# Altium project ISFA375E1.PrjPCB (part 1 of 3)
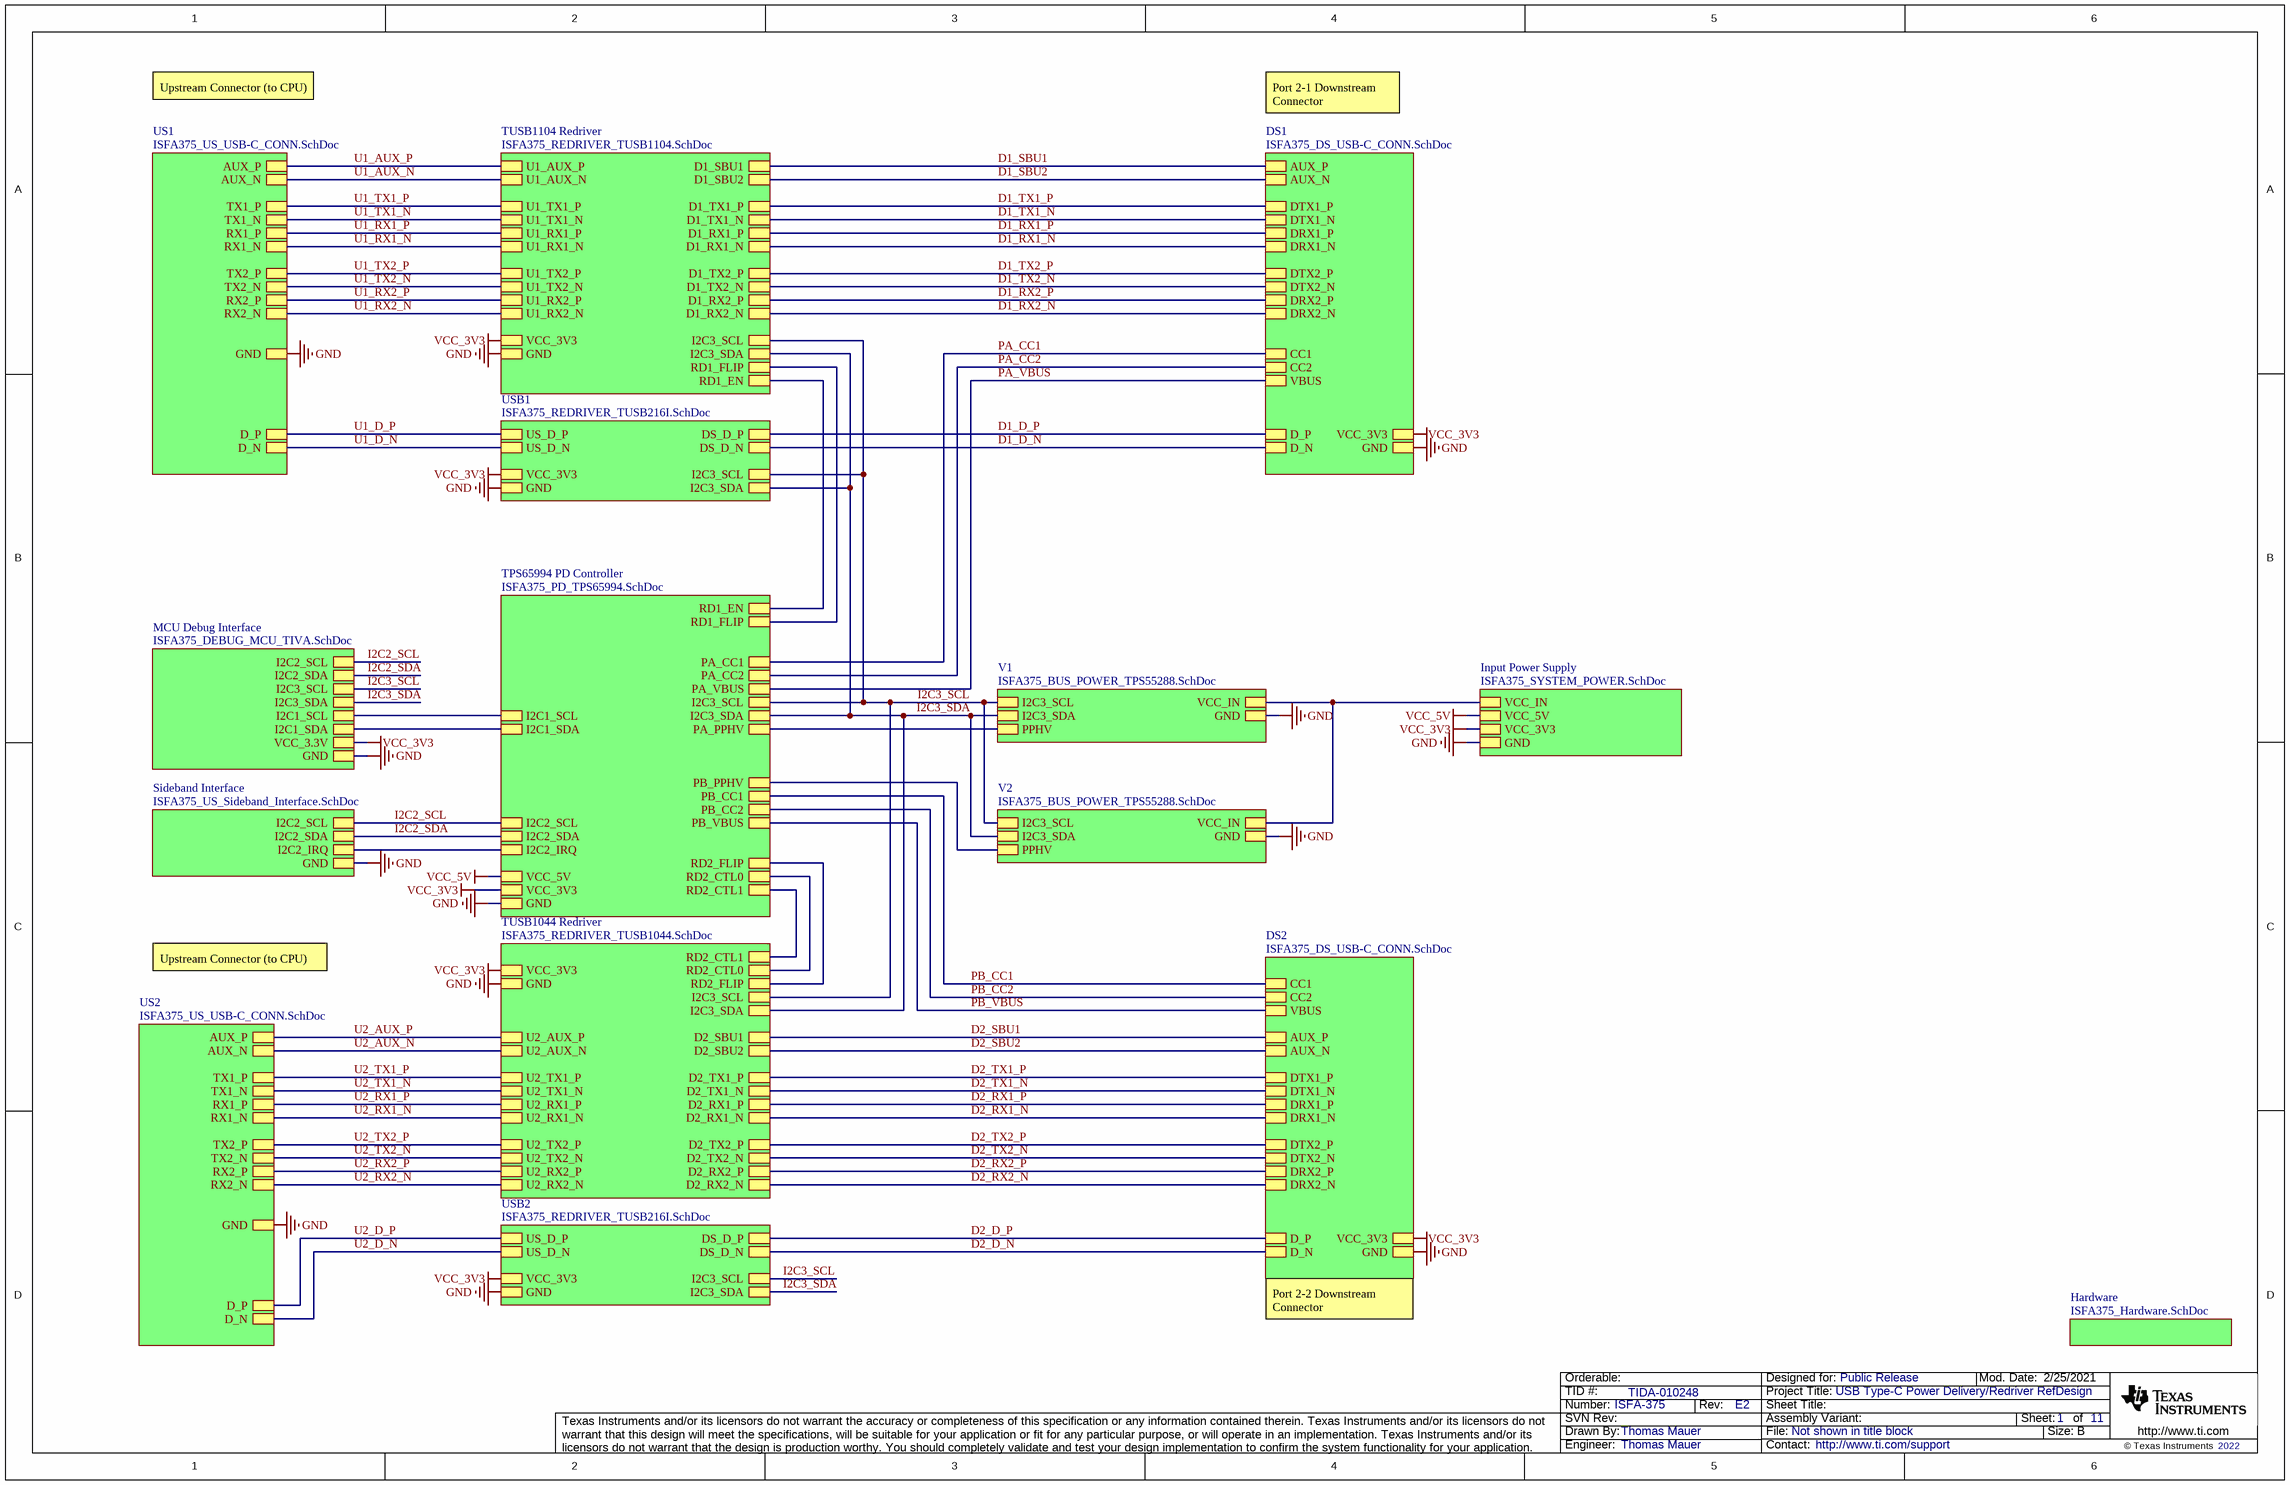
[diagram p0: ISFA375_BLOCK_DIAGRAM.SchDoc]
CopyrightYear: 2022; PCB_Layout: Preeti Udapudi; PCB_Rev: E2; PRJ_Customer: Public Release; PRJ_Engineer: Thomas Mauer; PRJ_Number: ISFA-375; PRJ_Title: USB Type-C Power Delivery/Redriver RefDesign; SCH_Rev: E2; TechSupport: http://www.ti.com/support; TID: TIDA-010248
12 sheets, 488 parts. Net scope: hierarchical (ports join the sheet entries above them; power ports are global).
Board file: ISFA375.PcbDoc
Sheets:
  ISFA375_BLOCK_DIAGRAM.SchDoc
    US1 = ISFA375_US_USB-C_CONN.SchDoc
    TPS65994 PD Controller = ISFA375_PD_TPS65994.SchDoc
    MCU Debug Interface = ISFA375_DEBUG_MCU_TIVA.SchDoc
    DS1 = ISFA375_DS_USB-C_CONN.SchDoc
    Input Power Supply = ISFA375_SYSTEM_POWER.SchDoc
    V1 = ISFA375_BUS_POWER_TPS55288.SchDoc
    V2 = ISFA375_BUS_POWER_TPS55288.SchDoc
    TUSB1104 Redriver = ISFA375_REDRIVER_TUSB1104.SchDoc
    TUSB1044 Redriver = ISFA375_REDRIVER_TUSB1044.SchDoc
    Hardware = ISFA375_Hardware.SchDoc
    Sideband Interface = ISFA375_US_Sideband_Interface.SchDoc
    USB1 = ISFA375_REDRIVER_TUSB216I.SchDoc
    USB2 = ISFA375_REDRIVER_TUSB216I.SchDoc
    US2 = ISFA375_US_USB-C_CONN.SchDoc
    DS2 = ISFA375_DS_USB-C_CONN.SchDoc

## Sheet ISFA375_BLOCK_DIAGRAM.SchDoc
size 431 x 279 mm; Date: Not shown in title block; ApprovedBy: Not shown in title block; CheckedBy: Not shown in title block; Author: Not shown in title block; CompanyName: Not shown in title block; DrawnBy: Thomas Mauer; Engineer: Not shown in title block; Organization: Not shown in title block; Address1: Not shown in title block; Address2: Not shown in title block; Address3: Not shown in title block; Address4: Not shown in title block; DocumentNumber: 1; Revision: Use project parameter SCH_Rev; SheetNumber: 1; SheetTotal: 11; PageSetup: Record=PageOptions¦CenterHorizontal=True¦CenterVertical=True¦PrintScale=1.00¦XCorrection=1.00¦YCorrection=1.00¦PrintKind=0¦BorderSize=5000000¦LeftOffset=0¦BottomOffset=0¦Orientation=2¦PaperLength=1000¦PaperWidth=1000¦Scale=100¦PaperSource=15¦PrintQuality=600¦MediaType=1¦DitherType=10¦PaperKind=Letter¦PrintScaleMode=1

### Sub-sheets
DS1 = ISFA375_DS_USB-C_CONN.SchDoc: VBUS, AUX_P, AUX_N, DTX1_P, DTX1_N, DRX1_P, DRX1_N, DTX2_P, DTX2_N, DRX2_P, DRX2_N, CC1, CC2, D_P, D_N, GND, VCC_3V3
DS2 = ISFA375_DS_USB-C_CONN.SchDoc: VBUS, AUX_P, AUX_N, DTX1_P, DTX1_N, DRX1_P, DRX1_N, DTX2_P, DTX2_N, DRX2_P, DRX2_N, CC1, CC2, D_P, D_N, GND, VCC_3V3
Hardware = ISFA375_Hardware.SchDoc: no entries
Input Power Supply = ISFA375_SYSTEM_POWER.SchDoc: VCC_IN, VCC_5V, VCC_3V3, GND
MCU Debug Interface = ISFA375_DEBUG_MCU_TIVA.SchDoc: GND, VCC_3.3V, I2C1_SCL, I2C1_SDA, I2C3_SCL, I2C3_SDA, I2C2_SCL, I2C2_SDA
Sideband Interface = ISFA375_US_Sideband_Interface.SchDoc: GND, I2C2_IRQ, I2C2_SCL, I2C2_SDA
TPS65994 PD Controller = ISFA375_PD_TPS65994.SchDoc: PA_VBUS, PB_VBUS, I2C3_SCL, I2C3_SDA, I2C1_SCL, I2C1_SDA, PA_CC1, PA_CC2, PB_PPHV, I2C2_SCL, I2C2_SDA, I2C2_IRQ, PB_CC1, PB_CC2, PA_PPHV, GND, VCC_5V, VCC_3V3, RD1_EN, RD2_CTL0, RD2_CTL1, RD2_FLIP, RD1_FLIP
TUSB1044 Redriver = ISFA375_REDRIVER_TUSB1044.SchDoc: U2_TX1_P, U2_TX1_N, U2_RX1_P, U2_RX1_N, U2_TX2_P, U2_TX2_N, U2_RX2_P, U2_RX2_N, U2_AUX_P, U2_AUX_N, D2_TX1_P, D2_TX1_N, D2_RX1_P, D2_RX1_N, D2_TX2_P, D2_TX2_N, D2_RX2_P, D2_RX2_N, D2_SBU1, D2_SBU2, I2C3_SCL, I2C3_SDA, GND, VCC_3V3, RD2_FLIP, RD2_CTL0, RD2_CTL1
TUSB1104 Redriver = ISFA375_REDRIVER_TUSB1104.SchDoc: U1_TX1_P, U1_TX1_N, U1_RX1_P, U1_RX1_N, U1_TX2_P, U1_TX2_N, U1_RX2_P, U1_RX2_N, U1_AUX_P, U1_AUX_N, D1_TX1_P, D1_TX1_N, D1_RX1_P, D1_RX1_N, D1_TX2_P, D1_TX2_N, D1_RX2_P, D1_RX2_N, D1_SBU1, D1_SBU2, I2C3_SCL, I2C3_SDA, GND, VCC_3V3, RD1_EN, RD1_FLIP
US1 = ISFA375_US_USB-C_CONN.SchDoc: AUX_P, AUX_N, TX1_P, TX1_N, RX1_P, RX1_N, TX2_P, TX2_N, RX2_P, RX2_N, D_P, D_N, GND
US2 = ISFA375_US_USB-C_CONN.SchDoc: AUX_P, AUX_N, TX1_P, TX1_N, RX1_P, RX1_N, TX2_P, TX2_N, RX2_P, RX2_N, D_P, D_N, GND
USB1 = ISFA375_REDRIVER_TUSB216I.SchDoc: US_D_N, US_D_P, DS_D_P, DS_D_N, I2C3_SCL, I2C3_SDA, GND, VCC_3V3
USB2 = ISFA375_REDRIVER_TUSB216I.SchDoc: US_D_N, US_D_P, DS_D_P, DS_D_N, I2C3_SCL, I2C3_SDA, GND, VCC_3V3
V1 = ISFA375_BUS_POWER_TPS55288.SchDoc: I2C3_SCL, I2C3_SDA, VCC_IN, GND, PPHV
V2 = ISFA375_BUS_POWER_TPS55288.SchDoc: PPHV, I2C3_SCL, I2C3_SDA, VCC_IN, GND

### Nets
GND: sheet US1/GND, sheet TPS65994 PD Controller/GND, sheet MCU Debug Interface/GND, sheet DS1/GND, sheet Input Power Supply/GND, sheet V1/GND, sheet V2/GND, sheet TUSB1104 Redriver/GND, sheet TUSB1044 Redriver/GND, sheet Sideband Interface/GND, sheet USB1/GND, sheet USB2/GND, sheet US2/GND, sheet DS2/GND
VCC_3V3: sheet TPS65994 PD Controller/VCC_3V3, sheet MCU Debug Interface/VCC_3.3V, sheet DS1/VCC_3V3, sheet Input Power Supply/VCC_3V3, sheet TUSB1104 Redriver/VCC_3V3, sheet TUSB1044 Redriver/VCC_3V3, sheet USB1/VCC_3V3, sheet USB2/VCC_3V3, sheet DS2/VCC_3V3  [project net VCC_3.3V]
VCC_5V: sheet TPS65994 PD Controller/VCC_5V, sheet Input Power Supply/VCC_5V
VCC_IN: sheet Input Power Supply/VCC_IN, sheet V1/VCC_IN, sheet V2/VCC_IN
D1_D_N: sheet DS1/D_N, sheet USB1/DS_D_N
D1_D_P: sheet DS1/D_P, sheet USB1/DS_D_P
D1_RX1_N: sheet DS1/DRX1_N, sheet TUSB1104 Redriver/D1_RX1_N
D1_RX1_P: sheet DS1/DRX1_P, sheet TUSB1104 Redriver/D1_RX1_P
D1_RX2_N: sheet DS1/DRX2_N, sheet TUSB1104 Redriver/D1_RX2_N
D1_RX2_P: sheet DS1/DRX2_P, sheet TUSB1104 Redriver/D1_RX2_P
D1_SBU1: sheet DS1/AUX_P, sheet TUSB1104 Redriver/D1_SBU1  [project net AUX_P]
D1_SBU2: sheet DS1/AUX_N, sheet TUSB1104 Redriver/D1_SBU2  [project net AUX_N]
D1_TX1_N: sheet DS1/DTX1_N, sheet TUSB1104 Redriver/D1_TX1_N
D1_TX1_P: sheet DS1/DTX1_P, sheet TUSB1104 Redriver/D1_TX1_P
D1_TX2_N: sheet DS1/DTX2_N, sheet TUSB1104 Redriver/D1_TX2_N
D1_TX2_P: sheet DS1/DTX2_P, sheet TUSB1104 Redriver/D1_TX2_P
D2_D_N: sheet USB2/DS_D_N, sheet DS2/D_N  [project net D1_D_N]
D2_D_P: sheet USB2/DS_D_P, sheet DS2/D_P  [project net D1_D_P]
D2_RX1_N: sheet TUSB1044 Redriver/D2_RX1_N, sheet DS2/DRX1_N
D2_RX1_P: sheet TUSB1044 Redriver/D2_RX1_P, sheet DS2/DRX1_P
D2_RX2_N: sheet TUSB1044 Redriver/D2_RX2_N, sheet DS2/DRX2_N
D2_RX2_P: sheet TUSB1044 Redriver/D2_RX2_P, sheet DS2/DRX2_P
D2_SBU1: sheet TUSB1044 Redriver/D2_SBU1, sheet DS2/AUX_P  [project net AUX_P]
D2_SBU2: sheet TUSB1044 Redriver/D2_SBU2, sheet DS2/AUX_N  [project net AUX_N]
D2_TX1_N: sheet TUSB1044 Redriver/D2_TX1_N, sheet DS2/DTX1_N
D2_TX1_P: sheet TUSB1044 Redriver/D2_TX1_P, sheet DS2/DTX1_P
D2_TX2_N: sheet TUSB1044 Redriver/D2_TX2_N, sheet DS2/DTX2_N
D2_TX2_P: sheet TUSB1044 Redriver/D2_TX2_P, sheet DS2/DTX2_P
I2C1_SCL: sheet TPS65994 PD Controller/I2C1_SCL, sheet MCU Debug Interface/I2C1_SCL
I2C1_SDA: sheet TPS65994 PD Controller/I2C1_SDA, sheet MCU Debug Interface/I2C1_SDA
I2C2_IRQ: sheet TPS65994 PD Controller/I2C2_IRQ, sheet Sideband Interface/I2C2_IRQ
I2C2_SCL: sheet TPS65994 PD Controller/I2C2_SCL, sheet MCU Debug Interface/I2C2_SCL, sheet Sideband Interface/I2C2_SCL
I2C2_SDA: sheet TPS65994 PD Controller/I2C2_SDA, sheet MCU Debug Interface/I2C2_SDA, sheet Sideband Interface/I2C2_SDA
I2C3_SCL: sheet TPS65994 PD Controller/I2C3_SCL, sheet MCU Debug Interface/I2C3_SCL, sheet V1/I2C3_SCL, sheet V2/I2C3_SCL, sheet TUSB1104 Redriver/I2C3_SCL, sheet TUSB1044 Redriver/I2C3_SCL, sheet USB1/I2C3_SCL, sheet USB2/I2C3_SCL
I2C3_SDA: sheet TPS65994 PD Controller/I2C3_SDA, sheet MCU Debug Interface/I2C3_SDA, sheet V1/I2C3_SDA, sheet V2/I2C3_SDA, sheet TUSB1104 Redriver/I2C3_SDA, sheet TUSB1044 Redriver/I2C3_SDA, sheet USB1/I2C3_SDA, sheet USB2/I2C3_SDA
PA_CC1: sheet TPS65994 PD Controller/PA_CC1, sheet DS1/CC1
PA_CC2: sheet TPS65994 PD Controller/PA_CC2, sheet DS1/CC2
PA_PPHV: sheet TPS65994 PD Controller/PA_PPHV, sheet V1/PPHV
PA_VBUS: sheet TPS65994 PD Controller/PA_VBUS, sheet DS1/VBUS
PB_CC1: sheet TPS65994 PD Controller/PB_CC1, sheet DS2/CC1
PB_CC2: sheet TPS65994 PD Controller/PB_CC2, sheet DS2/CC2
PB_PPHV: sheet TPS65994 PD Controller/PB_PPHV, sheet V2/PPHV
PB_VBUS: sheet TPS65994 PD Controller/PB_VBUS, sheet DS2/VBUS
RD1_EN: sheet TPS65994 PD Controller/RD1_EN, sheet TUSB1104 Redriver/RD1_EN
RD1_FLIP: sheet TPS65994 PD Controller/RD1_FLIP, sheet TUSB1104 Redriver/RD1_FLIP
RD2_CTL0: sheet TPS65994 PD Controller/RD2_CTL0, sheet TUSB1044 Redriver/RD2_CTL0
RD2_CTL1: sheet TPS65994 PD Controller/RD2_CTL1, sheet TUSB1044 Redriver/RD2_CTL1
RD2_FLIP: sheet TPS65994 PD Controller/RD2_FLIP, sheet TUSB1044 Redriver/RD2_FLIP
U1_AUX_N: sheet US1/AUX_N, sheet TUSB1104 Redriver/U1_AUX_N  [project net AUX_N]
U1_AUX_P: sheet US1/AUX_P, sheet TUSB1104 Redriver/U1_AUX_P  [project net AUX_P]
U1_D_N: sheet US1/D_N, sheet USB1/US_D_N  [project net D_N]
U1_D_P: sheet US1/D_P, sheet USB1/US_D_P  [project net D_P]
U1_RX1_N: sheet US1/RX1_N, sheet TUSB1104 Redriver/U1_RX1_N  [project net RX1_N]
U1_RX1_P: sheet US1/RX1_P, sheet TUSB1104 Redriver/U1_RX1_P  [project net RX1_P]
U1_RX2_N: sheet US1/RX2_N, sheet TUSB1104 Redriver/U1_RX2_N  [project net RX2_N]
U1_RX2_P: sheet US1/RX2_P, sheet TUSB1104 Redriver/U1_RX2_P  [project net RX2_P]
U1_TX1_N: sheet US1/TX1_N, sheet TUSB1104 Redriver/U1_TX1_N  [project net TX1_N]
U1_TX1_P: sheet US1/TX1_P, sheet TUSB1104 Redriver/U1_TX1_P  [project net TX1_P]
U1_TX2_N: sheet US1/TX2_N, sheet TUSB1104 Redriver/U1_TX2_N  [project net TX2_N]
U1_TX2_P: sheet US1/TX2_P, sheet TUSB1104 Redriver/U1_TX2_P  [project net TX2_P]
U2_AUX_N: sheet TUSB1044 Redriver/U2_AUX_N, sheet US2/AUX_N  [project net AUX_N]
U2_AUX_P: sheet TUSB1044 Redriver/U2_AUX_P, sheet US2/AUX_P  [project net AUX_P]
U2_D_N: sheet USB2/US_D_N, sheet US2/D_N  [project net D_N]
U2_D_P: sheet USB2/US_D_P, sheet US2/D_P  [project net D_P]
U2_RX1_N: sheet TUSB1044 Redriver/U2_RX1_N, sheet US2/RX1_N  [project net RX1_N]
U2_RX1_P: sheet TUSB1044 Redriver/U2_RX1_P, sheet US2/RX1_P  [project net RX1_P]
U2_RX2_N: sheet TUSB1044 Redriver/U2_RX2_N, sheet US2/RX2_N  [project net RX2_N]
U2_RX2_P: sheet TUSB1044 Redriver/U2_RX2_P, sheet US2/RX2_P  [project net RX2_P]
U2_TX1_N: sheet TUSB1044 Redriver/U2_TX1_N, sheet US2/TX1_N  [project net TX1_N]
U2_TX1_P: sheet TUSB1044 Redriver/U2_TX1_P, sheet US2/TX1_P  [project net TX1_P]
U2_TX2_N: sheet TUSB1044 Redriver/U2_TX2_N, sheet US2/TX2_N  [project net TX2_N]
U2_TX2_P: sheet TUSB1044 Redriver/U2_TX2_P, sheet US2/TX2_P  [project net TX2_P]

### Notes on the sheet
- Upstream Connector (to CPU)
- Port 2-1 Downstream Connector
- Port 2-2 Downstream Connector

## Sheet ISFA375_US_USB-C_CONN.SchDoc
size 431 x 279 mm; Date: Not shown in title block; ApprovedBy: Not shown in title block; CheckedBy: Not shown in title block; Author: Not shown in title block; CompanyName: Not shown in title block; DrawnBy: Thomas Mauer; Engineer: Not shown in title block; Organization: Not shown in title block; Address1: Not shown in title block; Address2: Not shown in title block; Address3: Not shown in title block; Address4: Not shown in title block; DocumentNumber: 2; Revision: Use project parameter SCH_Rev; SheetNumber: 2; SheetTotal: 11; PageSetup: Record=PageOptions¦CenterHorizontal=True¦CenterVertical=True¦PrintScale=1.00¦XCorrection=1.00¦YCorrection=1.00¦PrintKind=0¦BorderSize=5000000¦LeftOffset=0¦BottomOffset=0¦Orientation=2¦PaperLength=1000¦PaperWidth=1000¦Scale=100¦PaperSource=15¦PrintQuality=600¦MediaType=1¦DitherType=10¦PaperKind=Letter¦PrintScaleMode=1
Used 2 times, as channels US1, US2. Parts and nets are listed once, with the designators drawn on the sheet.
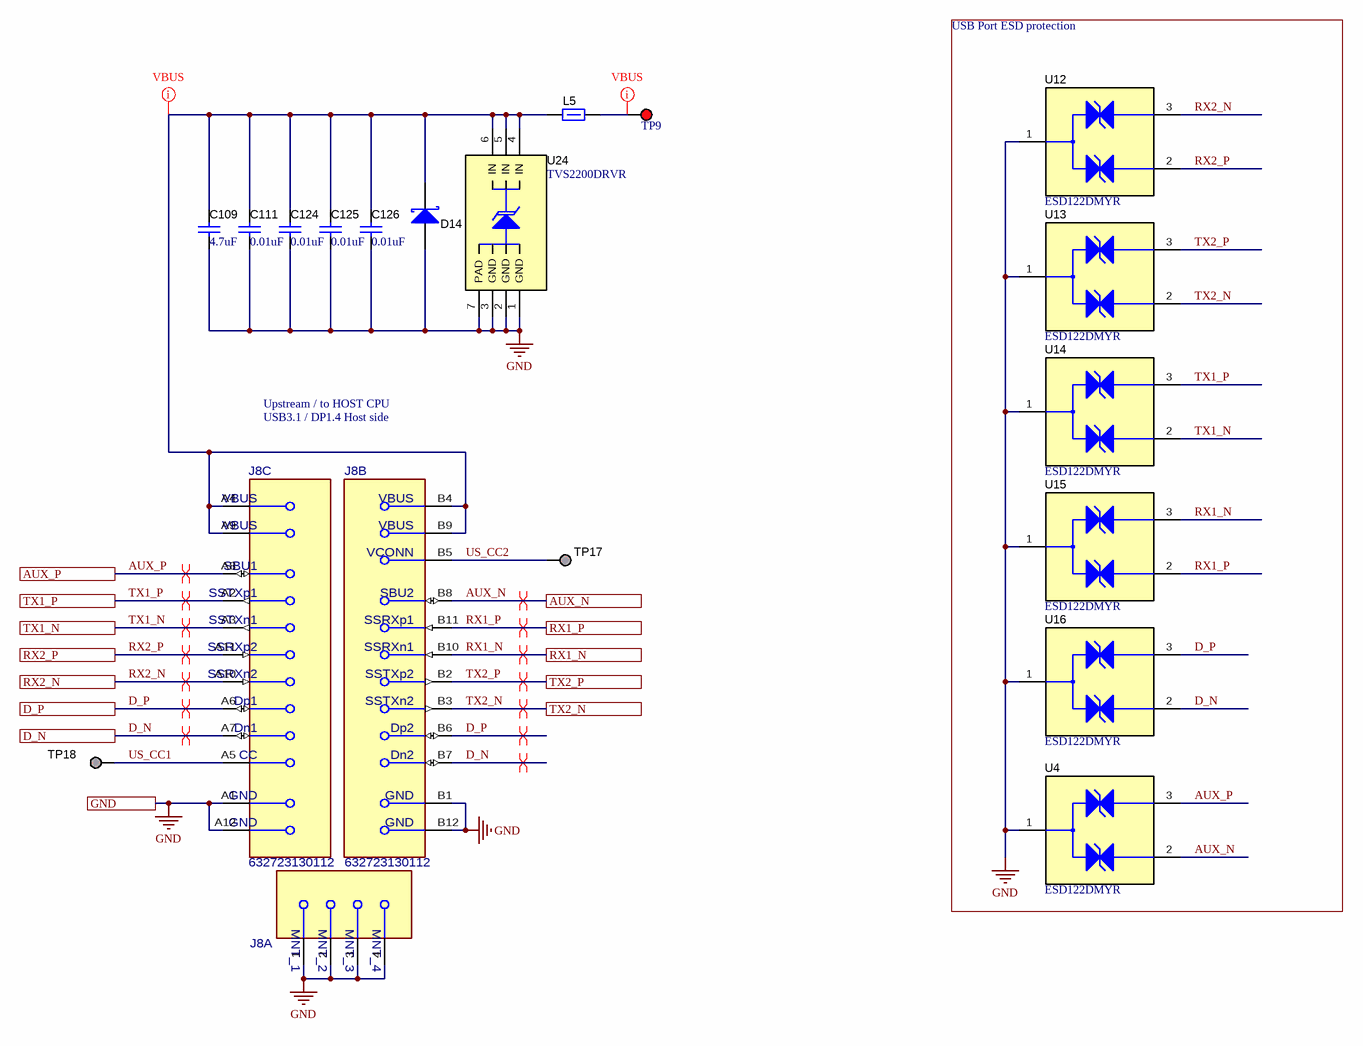
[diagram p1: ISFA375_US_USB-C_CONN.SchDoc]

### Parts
C109  ValueDisplayed: 4.7uF  [0603L]  (hidden comment: GRM188R6YA475KE15D)
C111  ValueDisplayed: 0.01uF  [0402L]  (hidden comment: C0402C103J5RACTU)
C124  ValueDisplayed: 0.01uF  [0402L]  (hidden comment: C0402C103J5RACTU)
C125  ValueDisplayed: 0.01uF  [0402L]  (hidden comment: C0402C103J5RACTU)
C126  ValueDisplayed: 0.01uF  [0402L]  (hidden comment: C0402C103J5RACTU)
D14  NSR20F30NXT5G  [DSN2_0603]  (value not drawn)
J8  632723130112  [FP-632723130112_CONN_USB_9MM65_10MM0-MFG]  (value not drawn)  (parts A,B,C of 3)
L5  742792021  [0805L]  (value not drawn)
TP9  5005  [Keystone5005]  (value not drawn)
TP17  TESTPOINT  [TP_25MIL-SMT]  (value not drawn)  (no BOM)
TP18  TESTPOINT  [TP_25MIL-SMT]  (value not drawn)  (no BOM)
U4  ESD122DMYR  [DMY0003A]
U12  ESD122DMYR  [DMY0003A]
U13  ESD122DMYR  [DMY0003A]
U14  ESD122DMYR  [DMY0003A]
U15  ESD122DMYR  [DMY0003A]
U16  ESD122DMYR  [DMY0003A]
U24  TVS2200DRVR  [DRV0006A]

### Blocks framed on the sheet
USB Port ESD protection: U4 U12-U16

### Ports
AUX_N, AUX_P, D_N, D_P, GND, RX1_N, RX1_P, RX2_N, RX2_P, TX1_N, TX1_P, TX2_N, TX2_P

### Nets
GND: C109.2 C111.2 C124.2 C125.2 C126.2 D14.2(A) J8.1(MNT_1) J8.2(MNT_2) J8.3(MNT_3) J8.4(MNT_4) J8.A1(GND) J8.A12(GND) J8.B1(GND) J8.B12(GND) U4.1(GND) U12.1(GND) U13.1(GND) U14.1(GND) U15.1(GND) U16.1(GND) U24.1(GND) U24.2(GND) U24.3(GND) U24.7(PAD) ; port GND
AUX_N: J8.B8(SBU2) U4.2(IO2) ; port AUX_N
AUX_P: J8.A8(SBU1) U4.3(IO1) ; port AUX_P
D_N: J8.A7(Dn1) J8.B7(Dn2) U16.2(IO2) ; port D_N
D_P: J8.A6(Dp1) J8.B6(Dp2) U16.3(IO1) ; port D_P
RX1_N: J8.B10(SSRXn1) U15.3(IO1) ; port RX1_N
RX1_P: J8.B11(SSRXp1) U15.2(IO2) ; port RX1_P
RX2_N: J8.A10(SSRXn2) U12.3(IO1) ; port RX2_N
RX2_P: J8.A11(SSRXp2) U12.2(IO2) ; port RX2_P
TX1_N: J8.A3(SSTXn1) U14.2(IO2) ; port TX1_N
TX1_P: J8.A2(SSTXp1) U14.3(IO1) ; port TX1_P
TX2_N: J8.B3(SSTXn2) U13.2(IO2) ; port TX2_N
TX2_P: J8.B2(SSTXp2) U13.3(IO1) ; port TX2_P
US_CC1: J8.A5(CC) TP18.1
US_CC2: J8.B5(VCONN) TP17.1
NetC109_1: C109.1 C111.1 C124.1 C125.1 C126.1 D14.1(K) J8.A4(VBUS) J8.A9(VBUS) J8.B4(VBUS) J8.B9(VBUS) L5.1 U24.4(IN) U24.5(IN) U24.6(IN)
NetL5_2: L5.2 TP9.1

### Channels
US1: designators end in _US1; ports AUX_N=AUX_N AUX_P=AUX_P D_N=D_N D_P=D_P GND=GND RX1_N=RX1_N RX1_P=RX1_P RX2_N=RX2_N RX2_P=RX2_P TX1_N=TX1_N TX1_P=TX1_P TX2_N=TX2_N TX2_P=TX2_P
US2: designators end in _US2; ports AUX_N=AUX_N AUX_P=AUX_P D_N=D_N D_P=D_P GND=GND RX1_N=RX1_N RX1_P=RX1_P RX2_N=RX2_N RX2_P=RX2_P TX1_N=TX1_N TX1_P=TX1_P TX2_N=TX2_N TX2_P=TX2_P

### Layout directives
differential pair; net class Diff_pairs: AUX_N, AUX_P, D_N, D_P, RX1_N, RX1_P, RX2_N, RX2_P, TX1_N, TX1_P, TX2_N, TX2_P
net class vbus: NetC109_US1_1, NetL5_US1_2

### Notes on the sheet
- USB3.1 / DP1.4 Host side
- Upstream / to HOST CPU

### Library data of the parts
C109 = CMP-0007357-5: CAP, CERM, 4.7 uF, 35 V, +/- 10%, X5R, 0603; Manufacturer: MuRata; TaMin_C: -55°C; Polarized: N; SizeAreaWB_mm2: 4.68; Value1: Unknown; U/M: EA; Value: 4.7uF; TaMax_C: 85°C; SizeZ_mm: 1; SizeX_mm: 1.6; SizeY_mm: 0.8; Cap_Case: 0603; Value2: 35V; SizeArea_mm2: 1.28; Cap_F: 4.7µF; AEC Category: Q200
C111 C124-C126 = CMP-0006236-2: CAP, CERM, 0.01 uF, 50 V, +/- 5%, X7R, 0402; Manufacturer: Kemet; TaMin_C: -55°C; Polarized: N; SizeAreaWB_mm2: 3; Value1: Unknown; U/M: EA; Value: 0.01uF; TaMax_C: 125°C; SizeZ_mm: 0.6; SizeX_mm: 1; SizeY_mm: 0.5; Cap_Case: 0402; Value2: 50V; Cap_F: 10nF; AEC Category: Q200
D14 = CMP-0028829-2: Diode, Schottky, 30 V, 2 A, 2-XFDFN; Manufacturer: ON Semiconductor; Value2: 0.48V; SizeY_mm: 0.8; Value: 30V; TJmax_C: 150°C; Green_Lifecycle: Not Set; SizeAreaWB_mm2: 4.68; Value1: 2A; SizeArea_mm2: 1.28; Green_REACh: Incomplete; AEC Category: Q101; SizeZ_mm: 0.31; Vf_V: 480mV; AEC Qualified: N; SizeX_mm: 1.6
J8 = CMP-0093331-1: USB-C (USB TYPE-C) USB 3.2 Gen 2 (USB 3.1 Gen 2, Superspeed + (USB 3.1)) Receptacle Connector 24 Position Board Edge, Cutout; Surface Mount; Through Hole, Right Angle; Manufacturer: Wurth Electronics; SizeZ_mm: 3.52mm; AEC Qualified: No; Is Female: yes; Usb Standard: USB 3.1; Voltage_V: 20V; Shrouded: true; ContactFinish: Gold,Nickel; Current_A: 5A; Conn Orientation: Horizontal
L5 = CMP-0003072-1: Ferrite Bead, 22 ohm @ 100 MHz, 6 A, 0805; Manufacturer: Wurth Elektronik; Ztyp@1GHz_Ohm: 40.219; ZTyp@100MHz_Ohm: 22; SizeAreaWB_mm2: 6.75; DCR_ohm: 8m; Value1: 0.008 ohm; Value: 22 ohm; Imax_A: 6A; SizeZ_mm: 1.45; SizeX_mm: 2; SizeY_mm: 1.25; SizeArea_mm2: 2.5
TP9 = CMP-0055142-1: Test Point, Compact, Red, TH; Manufacturer: Keystone; CNHeader: FALSE; Green_Lifecycle: Active; Green_REACh: Passed; ContactFinish: Silver; CT: TRUE
TP17 TP18 = CMP-0078143-3: TEST POINT.  No entry in BOM.
U4 U12-U16 = CMP-0013358-2: 2-Channel ESD Protection Diode for USB Type-C and HDMI 2.0, DMY0003A (X1SON-3); Manufacturer: Texas Instruments; SizeX_mm: 0.6; SizeY_mm: 1.3; CompType: IC; SizeZ_mm: 0.4; SizeArea_mm2: 0.78; SizeAreaWB_mm2: 3.68; U/M: EA
U24 = CMP-0077834-1: 22-V Precision Surge Protection Clamp, DRV0006A (WSON-6); Alternate Manufacturer: Texas Instruments; SizeAreaWB_mm2: 9.0; SizeZ_mm: 0.8; SizeX_mm: 2.0; SizeArea_mm2: 4.0; CompType: IC; AEC Qualified: N; AEC Category: Q200

## Sheet ISFA375_PD_TPS65994.SchDoc
size 431 x 279 mm; Date: Not shown in title block; ApprovedBy: Not shown in title block; CheckedBy: Not shown in title block; Author: Not shown in title block; CompanyName: Not shown in title block; DrawnBy: Thomas Mauer; Engineer: Not shown in title block; Organization: Not shown in title block; Address1: Not shown in title block; Address2: Not shown in title block; Address3: Not shown in title block; Address4: Not shown in title block; DocumentNumber: 7; Revision: Use project parameter SCH_Rev; SheetNumber: 7; SheetTotal: 11; PageSetup: Record=PageOptions¦CenterHorizontal=True¦CenterVertical=True¦PrintScale=1.00¦XCorrection=1.00¦YCorrection=1.00¦PrintKind=0¦BorderSize=5000000¦LeftOffset=0¦BottomOffset=0¦Orientation=2¦PaperLength=1000¦PaperWidth=1000¦Scale=100¦PaperSource=15¦PrintQuality=600¦MediaType=1¦DitherType=10¦PaperKind=Letter¦PrintScaleMode=1
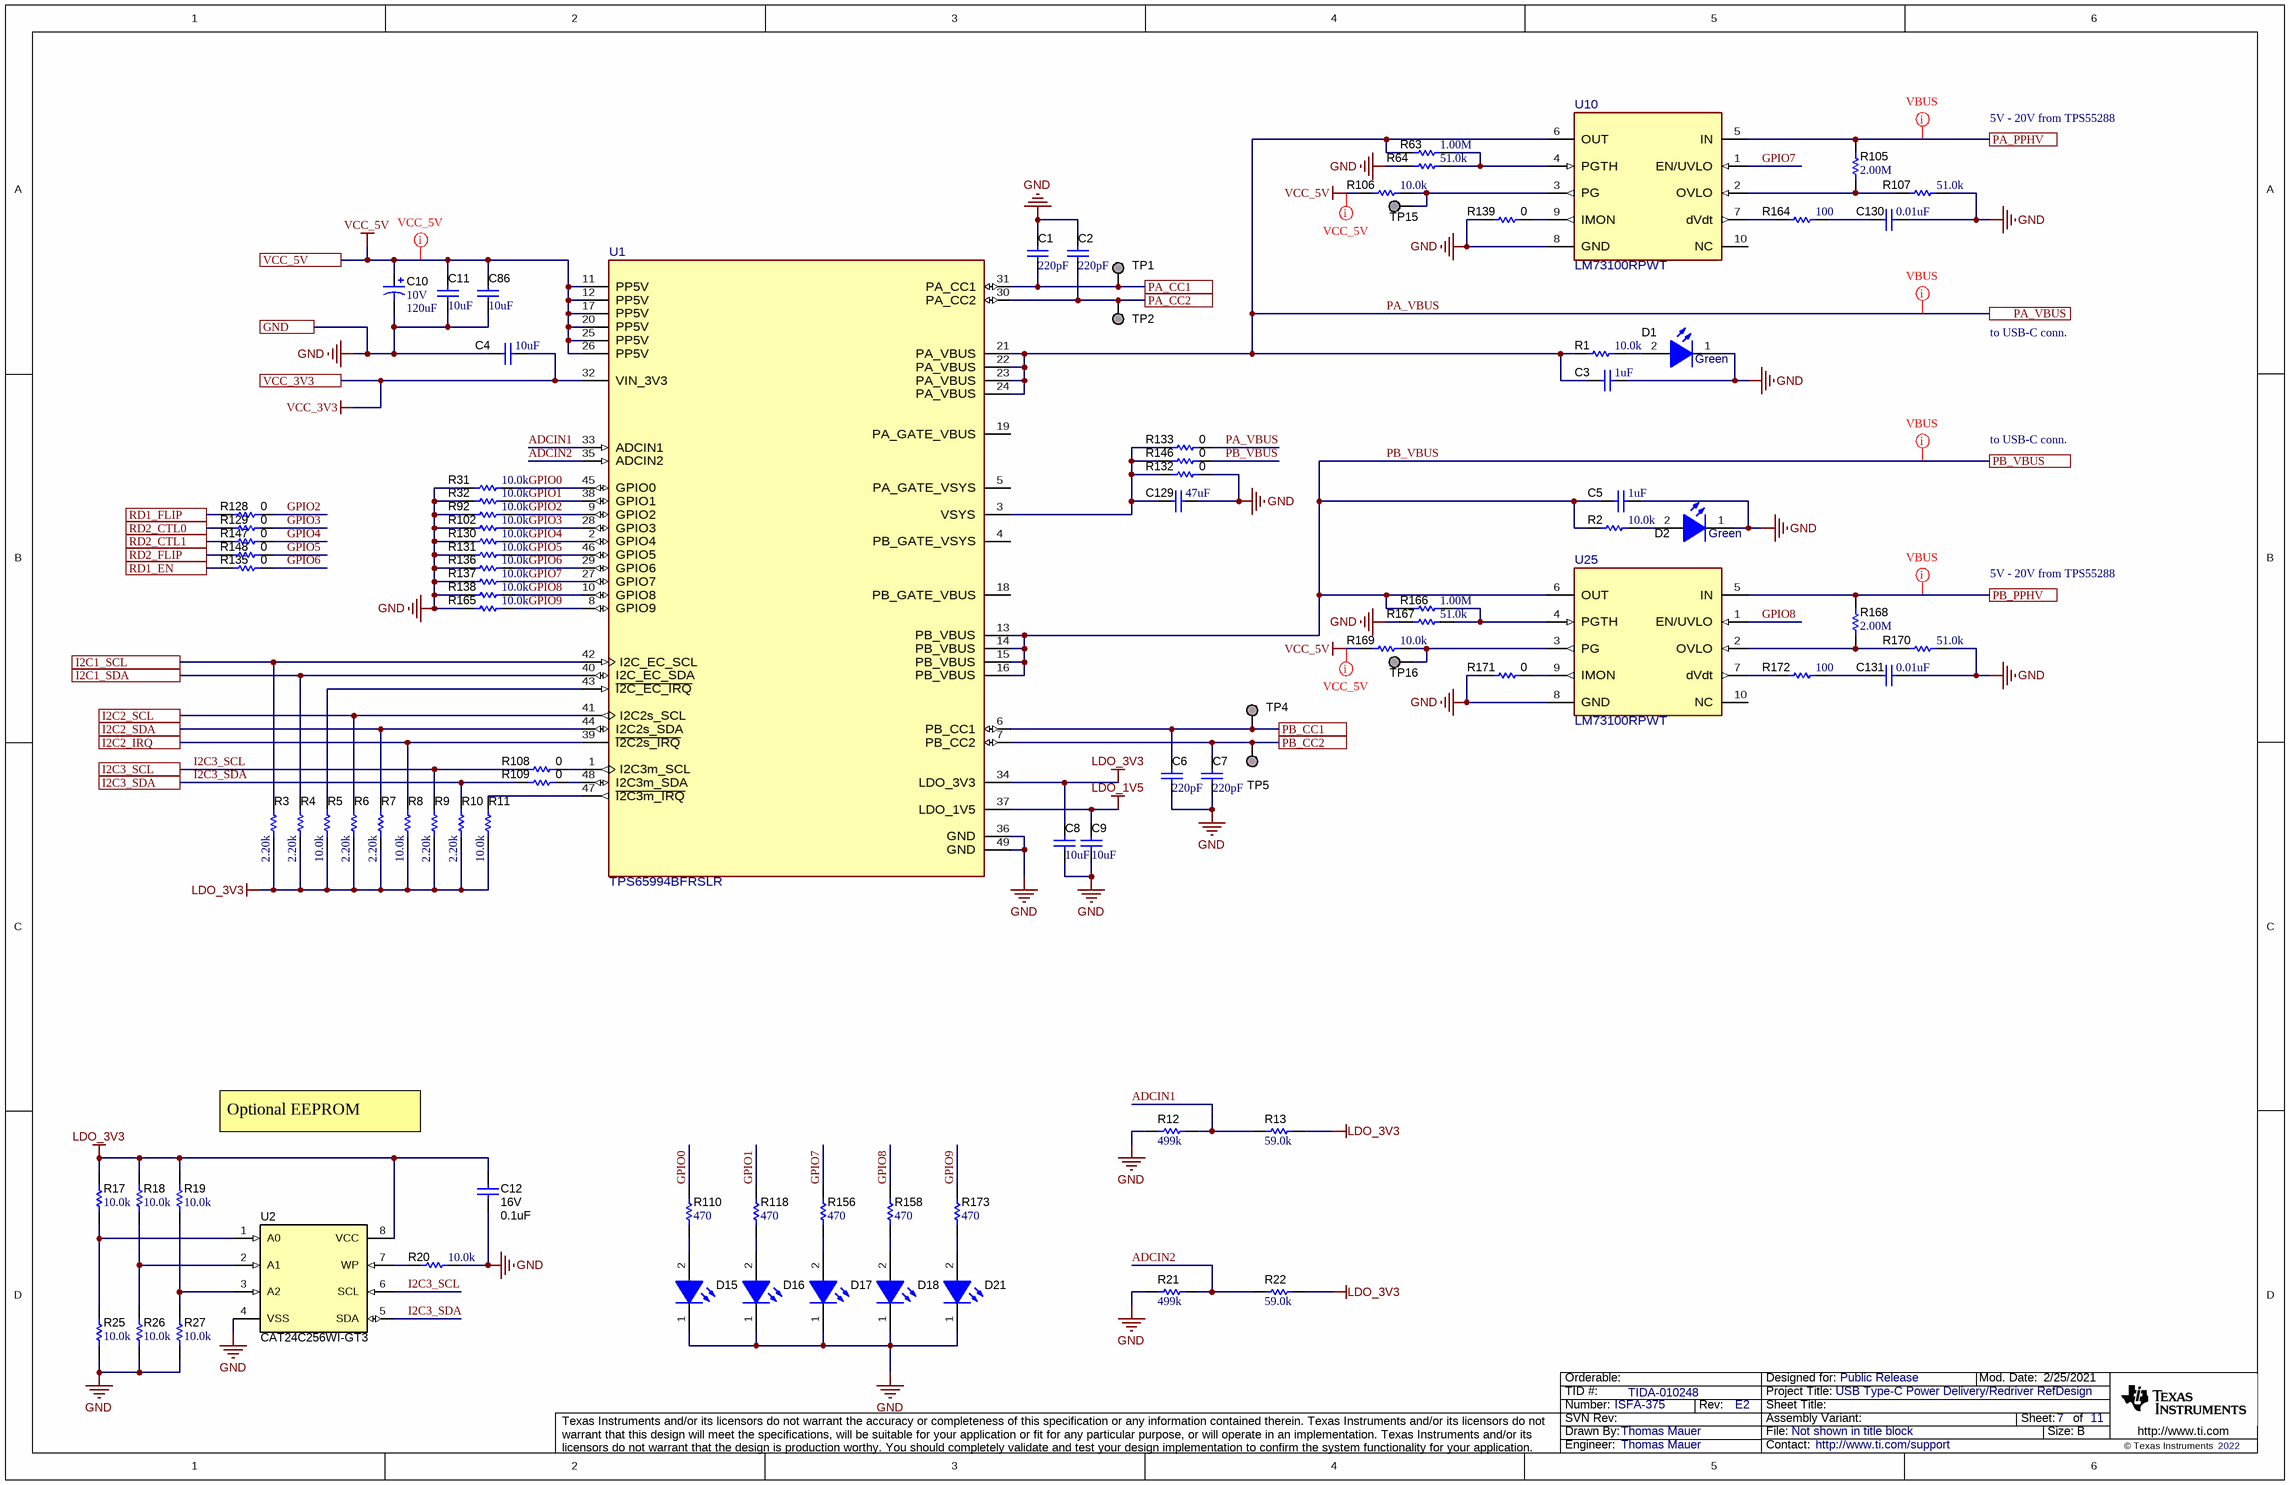
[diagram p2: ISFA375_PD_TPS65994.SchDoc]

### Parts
C1  ValueDisplayed: 220pF  [0201_033L]  (hidden comment: CGA1A2X7R1H221K030BA)
C2  ValueDisplayed: 220pF  [0201_033L]  (hidden comment: CGA1A2X7R1H221K030BA)
C3  ValueDisplayed: 1uF  [0402L]  (hidden comment: GRM155R6YA105KE11D)
C4  ValueDisplayed: 10uF  [0603L]  (hidden comment: GRM188R61E106MA73D)
C5  ValueDisplayed: 1uF  [0402L]  (hidden comment: GRM155R6YA105KE11D)
C6  ValueDisplayed: 220pF  [0201_033]  (hidden comment: CGA1A2X7R1H221K030BA)
C7  ValueDisplayed: 220pF  [0201_033]  (hidden comment: CGA1A2X7R1H221K030BA)
C8  ValueDisplayed: 10uF  [0603L]  (hidden comment: GRM188R61E106MA73D)
C9  ValueDisplayed: 10uF  [0603L]  (hidden comment: GRM188R61E106MA73D)
C10  VDC_V: 10V  ValueDisplayed: 120uF  [CAPSMT_62_F61]  (hidden comment: APXE100ARA121MF61G)
C11  ValueDisplayed: 10uF  [0603]  (hidden comment: GRM188R61E106MA73D)
C12  VDC_V: 16V  ValueDisplayed: 0.1uF  [0201_033L]  (hidden comment: GRM033C71C104KE14D)
C86  ValueDisplayed: 10uF  [0603]  (hidden comment: GRM188R61E106MA73D)
C129  ValueDisplayed: 47uF  [1206L]  (hidden comment: C3216JB1E476M160AC)
C130  ValueDisplayed: 0.01uF  [0402L]  (hidden comment: C0402C103J5RACTU)
C131  ValueDisplayed: 0.01uF  [0402L]  (hidden comment: C0402C103J5RACTU)
D1  value Green  [WL-SMCW_GREEN]  (hidden comment: 150060VS75000)
D2  value Green  [WL-SMCW_GREEN]  (hidden comment: 150060VS75000)
D15  150060VS75000  [WL-SMCW_GREEN]  (value not drawn)
D16  150060VS75000  [WL-SMCW_GREEN]  (value not drawn)
D17  150060VS75000  [WL-SMCW_GREEN]  (value not drawn)
D18  150060VS75000  [WL-SMCW_GREEN]  (value not drawn)
D21  150060VS75000  [WL-SMCW_GREEN]  (value not drawn)
R1  ValueDisplayed: 10.0k  [0201L]  (hidden comment: CRCW020110K0FKED)
R2  ValueDisplayed: 10.0k  [0201L]  (hidden comment: CRCW020110K0FKED)
R3  ValueDisplayed: 2.20k  [0201L]  (hidden comment: CRCW02012K20FKED)
R4  ValueDisplayed: 2.20k  [0201L]  (hidden comment: CRCW02012K20FKED)
R5  ValueDisplayed: 10.0k  [0201L]  (hidden comment: CRCW020110K0FKED)
R6  ValueDisplayed: 2.20k  [0201L]  (hidden comment: CRCW02012K20FKED)
R7  ValueDisplayed: 2.20k  [0201L]  (hidden comment: CRCW02012K20FKED)
R8  ValueDisplayed: 10.0k  [0201L]  (hidden comment: CRCW020110K0FKED)
R9  ValueDisplayed: 2.20k  [0201L]  (hidden comment: CRCW02012K20FKED)
R10  ValueDisplayed: 2.20k  [0201L]  (hidden comment: CRCW02012K20FKED)
R11  ValueDisplayed: 10.0k  [0201L]  (hidden comment: CRCW020110K0FKED)
R12  ValueDisplayed: 499k  [0201L]  (hidden comment: RC0201FR-07499KL)
R13  ValueDisplayed: 59.0k  [0201L]  (hidden comment: RC0201FR-0759KL)
R17  ValueDisplayed: 10.0k  [0201L]  (hidden comment: CRCW020110K0FKED)
R18  ValueDisplayed: 10.0k  [0201L]  (hidden comment: CRCW020110K0FKED)
R19  ValueDisplayed: 10.0k  [0201L]  (hidden comment: CRCW020110K0FKED)
R20  ValueDisplayed: 10.0k  [0201L]  (hidden comment: CRCW020110K0FKED)
R21  ValueDisplayed: 499k  [0201L]  (hidden comment: RC0201FR-07499KL)
R22  ValueDisplayed: 59.0k  [0201L]  (hidden comment: RC0201FR-0759KL)
R25  ValueDisplayed: 10.0k  [0201L]  (hidden comment: CRCW020110K0FKED)
R26  ValueDisplayed: 10.0k  [0201L]  (hidden comment: CRCW020110K0FKED)
R27  ValueDisplayed: 10.0k  [0201L]  (hidden comment: CRCW020110K0FKED)
R31  ValueDisplayed: 10.0k  [0201L]  (hidden comment: CRCW020110K0FKED)
R32  ValueDisplayed: 10.0k  [0201L]  (hidden comment: CRCW020110K0FKED)
R63  ValueDisplayed: 1.00M  [0201L]  (hidden comment: RC0201FR-7D1ML)
R64  ValueDisplayed: 51.0k  [0201L]  (hidden comment: RC0201FR-7D124KL)
R92  ValueDisplayed: 10.0k  [0201L]  (hidden comment: CRCW020110K0FKED)
R102  ValueDisplayed: 10.0k  [0201L]  (hidden comment: CRCW020110K0FKED)
R105  ValueDisplayed: 2.00M  [0201L]  (hidden comment: RC0201FR-072ML)
R106  ValueDisplayed: 10.0k  [0201L]  (hidden comment: CRCW020110K0FKED)
R107  ValueDisplayed: 51.0k  [0201L]  (hidden comment: RC0201FR-07931KL)
R108  ValueDisplayed: 0  [0201L]  (hidden comment: CRCW02010000Z0ED)
R109  ValueDisplayed: 0  [0201L]  (hidden comment: CRCW02010000Z0ED)
R110  ValueDisplayed: 470  [0201L]  (hidden comment: RC0201FR-07470RL)
R118  ValueDisplayed: 470  [0201L]  (hidden comment: RC0201FR-07470RL)
R128  ValueDisplayed: 0  [0201L]  (hidden comment: CRCW02010000Z0ED)
R129  ValueDisplayed: 0  [0201L]  (hidden comment: CRCW02010000Z0ED)
R130  ValueDisplayed: 10.0k  [0201L]  (hidden comment: CRCW020110K0FKED)
R131  ValueDisplayed: 10.0k  [0201L]  (hidden comment: CRCW020110K0FKED)
R132  ValueDisplayed: 0  [0201L]  (hidden comment: CRCW02010000Z0ED)
R133  ValueDisplayed: 0  [0201L]  (hidden comment: CRCW02010000Z0ED)
R135  ValueDisplayed: 0  [0201L]  (hidden comment: CRCW02010000Z0ED)
R136  ValueDisplayed: 10.0k  [0201L]  (hidden comment: CRCW020110K0FKED)
R137  ValueDisplayed: 10.0k  [0201L]  (hidden comment: CRCW020110K0FKED)
R138  ValueDisplayed: 10.0k  [0201L]  (hidden comment: CRCW020110K0FKED)
R139  ValueDisplayed: 0  [0201L]  (hidden comment: CRCW02010000Z0ED)
R146  ValueDisplayed: 0  [0201L]  (hidden comment: CRCW02010000Z0ED)
R147  ValueDisplayed: 0  [0201L]  (hidden comment: CRCW02010000Z0ED)
R148  ValueDisplayed: 0  [0201L]  (hidden comment: CRCW02010000Z0ED)
R156  ValueDisplayed: 470  [0201L]  (hidden comment: RC0201FR-07470RL)
R158  ValueDisplayed: 470  [0201L]  (hidden comment: RC0201FR-07470RL)
R164  ValueDisplayed: 100  [0201L]  (hidden comment: CRCW0201100RFKED)
R165  ValueDisplayed: 10.0k  [0201L]  (hidden comment: CRCW020110K0FKED)
R166  ValueDisplayed: 1.00M  [0201L]  (hidden comment: RC0201FR-7D1ML)
R167  ValueDisplayed: 51.0k  [0201L]  (hidden comment: RC0201FR-7D124KL)
R168  ValueDisplayed: 2.00M  [0201L]  (hidden comment: RC0201FR-072ML)
R169  ValueDisplayed: 10.0k  [0201L]  (hidden comment: CRCW020110K0FKED)
R170  ValueDisplayed: 51.0k  [0201L]  (hidden comment: RC0201FR-07931KL)
R171  ValueDisplayed: 0  [0201L]  (hidden comment: CRCW02010000Z0ED)
R172  ValueDisplayed: 100  [0201L]  (hidden comment: CRCW0201100RFKED)
R173  ValueDisplayed: 470  [0201L]  (hidden comment: RC0201FR-07470RL)
TP1  TESTPOINT  [TP_25MIL-SMT]  (value not drawn)  (no BOM)
TP2  TESTPOINT  [TP_25MIL-SMT]  (value not drawn)  (no BOM)
TP4  TESTPOINT  [TP_25MIL-SMT]  (value not drawn)  (no BOM)
TP5  TESTPOINT  [TP_25MIL-SMT]  (value not drawn)  (no BOM)
TP15  TESTPOINT  [TP_25MIL-SMT]  (value not drawn)  (no BOM)
TP16  TESTPOINT  [TP_25MIL-SMT]  (value not drawn)  (no BOM)
U1  TPS65994BFRSLR  [RSL0048B-MFG]
U2  CAT24C256WI-GT3  [SOIC-8]
U10  LM73100RPWT  [-MFG]
U25  LM73100RPWT  [-MFG]

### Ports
GND, I2C1_SCL, I2C1_SDA, I2C2_IRQ, I2C2_SCL, I2C2_SDA, I2C3_SCL, I2C3_SDA, PA_CC1, PA_CC2, PA_PPHV, PA_VBUS, PB_CC1, PB_CC2, PB_PPHV, PB_VBUS, RD1_EN, RD1_FLIP, RD2_CTL0, RD2_CTL1, RD2_FLIP, VCC_3V3, VCC_5V

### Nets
GND: C1.1 C2.1 C3.2 C4.2 C5.2 C6.2 C7.2 C8.1 C9.1 C10.2(-) C11.2 C12.2 C86.2 C129.1 C130.1 C131.1 D1.1(K) D2.1(K) D15.1(K) D16.1(K) D17.1(K) D18.1(K) D21.1(K) R12.1 R20.1 R21.1 R25.1 R26.1 R27.1 R31.2 R32.2 R64.1 R92.2 R102.2 R107.2 R130.2 R131.2 R132.2 R136.2 R137.2 R138.2 R139.1 R165.2 R167.1 R170.2 R171.1 U1.36(GND) U1.49(GND) U2.4(VSS) U10.8(GND) U25.8(GND) ; port GND
LDO_1V5: C9.2 U1.37(LDO_1V5)
LDO_3V3: C8.2 C12.1 R3.1 R4.1 R5.1 R6.1 R7.1 R8.1 R9.1 R10.1 R11.1 R13.2 R17.2 R18.2 R19.2 R22.2 U1.34(LDO_3V3) U2.8(VCC)
VCC_3V3: C4.1 U1.32(VIN_3V3) ; port VCC_3V3  [project net VCC_3.3V]
VCC_5V: C10.1(+) C11.1 C86.1 R106.1 R169.1 U1.11(PP5V) U1.12(PP5V) U1.17(PP5V) U1.20(PP5V) U1.25(PP5V) U1.26(PP5V) ; port VCC_5V
ADCIN1: R12.2 R13.1 U1.33(ADCIN1)
ADCIN2: R21.2 R22.1 U1.35(ADCIN2)
GPIO0: R31.1 R110.2 U1.45(GPIO0)
GPIO1: R32.1 R118.2 U1.38(GPIO1)
GPIO2: R92.1 R128.2 U1.9(GPIO2)
GPIO3: R102.1 R129.2 U1.28(GPIO3)
GPIO4: R130.1 R147.2 U1.2(GPIO4)
GPIO5: R131.1 R148.2 U1.46(GPIO5)
GPIO6: R135.2 R136.1 U1.29(GPIO6)
GPIO7: R137.1 R156.2 U1.27(GPIO7) U10.1(EN/UVLO)
GPIO8: R138.1 R158.2 U1.10(GPIO8) U25.1(EN/UVLO)
GPIO9: R165.1 R173.2 U1.8(GPIO9)
I2C1_SCL: R3.2 U1.42(I2C_EC_SCL) ; port I2C1_SCL
I2C1_SDA: R4.2 U1.40(I2C_EC_SDA) ; port I2C1_SDA
I2C2_IRQ: R8.2 U1.39(~{I2C2s_IRQ}) ; port I2C2_IRQ
I2C2_SCL: R6.2 U1.41(I2C2s_SCL) ; port I2C2_SCL
I2C2_SDA: R7.2 U1.44(I2C2s_SDA) ; port I2C2_SDA
I2C3_SCL: R9.2 R108.1 U2.6(SCL) ; port I2C3_SCL
I2C3_SDA: R10.2 R109.1 U2.5(SDA) ; port I2C3_SDA
PA_CC1: C1.2 TP1.1 U1.31(PA_CC1) ; port PA_CC1
PA_CC2: C2.2 TP2.1 U1.30(PA_CC2) ; port PA_CC2
PA_PPHV: R105.2 U10.5(IN) ; port PA_PPHV
PA_VBUS: C3.1 R1.1 R63.1 R133.2 U1.21(PA_VBUS) U1.22(PA_VBUS) U1.23(PA_VBUS) U1.24(PA_VBUS) U10.6(OUT) ; port PA_VBUS
PB_CC1: C6.1 TP4.1 U1.6(PB_CC1) ; port PB_CC1
PB_CC2: C7.1 TP5.1 U1.7(PB_CC2) ; port PB_CC2
PB_PPHV: R168.2 U25.5(IN) ; port PB_PPHV
PB_VBUS: C5.1 R2.1 R146.2 R166.1 U1.13(PB_VBUS) U1.14(PB_VBUS) U1.15(PB_VBUS) U1.16(PB_VBUS) U25.6(OUT) ; port PB_VBUS
RD1_EN: R135.1 ; port RD1_EN
RD1_FLIP: R128.1 ; port RD1_FLIP
RD2_CTL0: R129.1 ; port RD2_CTL0
RD2_CTL1: R147.1 ; port RD2_CTL1
RD2_FLIP: R148.1 ; port RD2_FLIP
NetC129_2: C129.2 R132.1 R133.1 R146.1 U1.3(VSYS)
NetC130_2: C130.2 R164.2
NetC131_2: C131.2 R172.2
NetD1_2: D1.2(A) R1.2
NetD2_2: D2.2(A) R2.2
NetD15_2: D15.2(A) R110.1
NetD16_2: D16.2(A) R118.1
NetD17_2: D17.2(A) R156.1
NetD18_2: D18.2(A) R158.1
NetD21_2: D21.2(A) R173.1
NetR5_2: R5.2 U1.43(~{I2C_EC_IRQ})
NetR11_2: R11.2 U1.47(~{I2C3m_IRQ})
NetR17_1: R17.1 R25.2 U2.1(A0)
NetR18_1: R18.1 R26.2 U2.2(A1)
NetR19_1: R19.1 R27.2 U2.3(A2)
NetR20_2: R20.2 U2.7(WP)
NetR63_2: R63.2 R64.2 U10.4(PGTH)
NetR105_1: R105.1 R107.1 U10.2(OVLO)
NetR106_2: R106.2 TP15.1 U10.3(PG)
NetR108_2: R108.2 U1.1(I2C3m_SCL)
NetR109_2: R109.2 U1.48(I2C3m_SDA)
NetR139_2: R139.2 U10.9(IMON)
NetR164_1: R164.1 U10.7(dVdt)
NetR166_2: R166.2 R167.2 U25.4(PGTH)
NetR168_1: R168.1 R170.1 U25.2(OVLO)
NetR169_2: R169.2 TP16.1 U25.3(PG)
NetR171_2: R171.2 U25.9(IMON)
NetR172_1: R172.1 U25.7(dVdt)

Not connected (* = marked no-connect by the designer): U1 4(PB_GATE_VSYS) 5(PA_GATE_VSYS) 18(PB_GATE_VBUS) 19(PA_GATE_VBUS); U10 10(NC); U25 10(NC)

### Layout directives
net class vbus: PA_PPHV, PA_VBUS, PB_PPHV, PB_VBUS
net class VCC_5V: VCC_5V

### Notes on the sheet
- 5V - 20V from TPS55288
- to USB-C conn.
- Optional EEPROM

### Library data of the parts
C1 C2 = CMP-0009652-3: CAP, CERM, 220 pF, 50 V, +/- 10%, X7R, AEC-Q200 Grade 1, 0201; Manufacturer: TDK; TaMin_C: -55°C; ESR_ohm: 11.6275; Polarized: N; SizeAreaWB_mm2: 2.08; Value1: 11.6275 ohm; U/M: EA; Value: 220pF; TaMax_C: 125°C; SizeZ_mm: 0.33; SizeX_mm: 0.6; SizeY_mm: 0.3; Cap_Case: 0201_033; Value2: 50V; SizeArea_mm2: 0.18; AEC Qualified: Y; IRMS_A: 2.00785dA; AEC Grade: 1; AEC Category: Q200
C3 C5 = CMP-0006619-2: CAP, CERM, 1 uF, 35 V, +/- 10%, X5R, 0402; Manufacturer: MuRata; TaMin_C: -55°C; Polarized: N; SizeAreaWB_mm2: 3; Value1: Unknown; U/M: EA; Value: 1uF; TaMax_C: 85°C; SizeZ_mm: 0.6; SizeX_mm: 1; SizeY_mm: 0.5; Cap_Case: 0402; Value2: 35V; Cap_F: 1µF; AEC Category: Q200
C4 C8 C9 = CMP-0007344-5: CAP, CERM, 10 uF, 25 V, +/- 20%, X5R, 0603; Manufacturer: MuRata; TaMin_C: -55°C; Polarized: N; SizeAreaWB_mm2: 4.68; Value1: Unknown; U/M: EA; Value: 10uF; TaMax_C: 85°C; SizeZ_mm: 1; SizeX_mm: 1.6; SizeY_mm: 0.8; Cap_Case: 0603; Value2: 25V; SizeArea_mm2: 1.28; Cap_F: 10µF; AEC Category: Q200
C6 C7 = CMP-0009652-3: CAP, CERM, 220 pF, 50 V, +/- 10%, X7R, AEC-Q200 Grade 1, 0201; Manufacturer: TDK; TaMin_C: -55°C; ESR_ohm: 11.6275; Polarized: N; SizeAreaWB_mm2: 2.08; Value1: 11.6275 ohm; U/M: EA; Value: 220pF; TaMax_C: 125°C; SizeZ_mm: 0.33; SizeX_mm: 0.6; SizeY_mm: 0.3; Value2: 50V; SizeArea_mm2: 0.18; AEC Qualified: Y; IRMS_A: 2.00785dA; AEC Grade: 1; AEC Category: Q200
C10 = CMP-0010560-1: CAP, AL, 120 uF, 10 V, +/- 20%, 0.025 ohm, SMD; Manufacturer: Chemi-Con; TaMin_C: -55°C; ESR_ohm: 0.025; Polarized: Y; SizeAreaWB_mm2: 73.96; U/M: EA; Value: 120uF; TaMax_C: 105°C; SizeZ_mm: 5.8; SizeX_mm: 6.6; Cap_Case: F61; SizeArea_mm2: 43.56; CompType: Capacitor; Cap_F: 120µF; IRMS_A: 2.53A; AEC Category: Q200
C11 C86 = CMP-0007344-5: CAP, CERM, 10 uF, 25 V, +/- 20%, X5R, 0603; Manufacturer: MuRata; TaMin_C: -55°C; Polarized: N; SizeAreaWB_mm2: 4.68; Value1: Unknown; U/M: EA; Value: 10uF; TaMax_C: 85°C; SizeZ_mm: 1; SizeX_mm: 1.6; SizeY_mm: 0.8; Value2: 25V; SizeArea_mm2: 1.28; Cap_F: 10µF; AEC Category: Q200
C12 = CMP-0009670-3: CAP, CERM, 0.1 uF, 16 V, +/- 10%, X5R, 0201; Manufacturer: MuRata; TaMin_C: -55°C; Polarized: N; SizeAreaWB_mm2: 2.08; Value1: Unknown; U/M: EA; Value: 0.1uF; TaMax_C: 125°C; SizeZ_mm: 0.33; SizeX_mm: 0.6; SizeY_mm: 0.3; Cap_Case: 0201; SizeArea_mm2: 0.18; Cap_F: 100nF; AEC Category: Q200
C129 = CMP-0008646-2: CAP, CERM, 47 uF, 25 V, +/- 20%, JB, 1206; Manufacturer: TDK; TaMin_C: -55°C; Polarized: N; SizeAreaWB_mm2: 10.92; Value1: Unknown; U/M: EA; Value: 47uF; TaMax_C: 85°C; SizeZ_mm: 1.35; SizeX_mm: 3.2; SizeY_mm: 1.6; Cap_Case: 1206; Value2: 25V; SizeArea_mm2: 5.12; Cap_F: 47µF; AEC Category: Q200
C130 C131 = CMP-0006236-2: as C111 on sheet ISFA375_US_USB-C_CONN
D1 D2 D15-D18 D21 = CMP-0002894-2: LED, Green, SMD; Manufacturer: Wurth Elektronik; Type: AlInGaP; Value2: 2V; Io_A: 20mA; Value1: W
R1 R2 R5 R8 R11 R17-R20 R25-R27 R31 R32 R92 R102 R106 R130 R131 R136-R138 R165 R169 = CMP-0027262-3: RES, 10.0 k, 1%, 0.05 W, 0201; Manufacturer: Vishay-Dale; Power_W: 50mW; TempCo: 100 ppm/C; Value_Code: 10k0; Value: 10.0k; EIA_Code: E96; Res_ohm: 10k; SizeX_mm: 0.6; SizeY_mm: 0.3; SizeZ_mm: 0.26; Value2: 0.05W; SizeArea_mm2: 0.18; AEC Qualified: N; VDC_V: 30V; AEC Category: Q200
R3 R4 R6 R7 R9 R10 = CMP-0027272-3: RES, 2.20 k, 1%, 0.05 W, 0201; Manufacturer: Vishay-Dale; Power_W: 50mW; TempCo: 100 ppm/C; Value_Code: 2k20; Value: 2.20k; Res_ohm: 2.2k; SizeX_mm: 0.6; SizeY_mm: 0.3; SizeZ_mm: 0.26; Value2: 0.05W; SizeArea_mm2: 0.18; AEC Qualified: N; VDC_V: 30V; AEC Category: Q200
R12 R21 = CMP-0027730-1: RES, 499 k, 1%, 0.05 W, 0201; Manufacturer: Yageo America; Power_W: 50mW; TempCo: 200 ppm/C; U/M: EA; Value: 499k; EIA_Code: E96; SizeX_mm: 0.6; SizeY_mm: 0.3; SizeZ_mm: 0.26; Value2: 0.05W; SizeArea_mm2: 0.18; AEC Qualified: N; VDC_V: 25V; AEC Category: Q200
R13 R22 = CMP-0027786-1: RES, 59.0 k, 1%, 0.05 W, 0201; Manufacturer: Yageo America; Power_W: 50mW; TempCo: 200 ppm/C; Value_Code: 59k0; U/M: EA; Value: 59.0k; EIA_Code: E96; Res_ohm: 59k; SizeX_mm: 0.6; SizeY_mm: 0.3; SizeZ_mm: 0.26; Value2: 0.05W; SizeArea_mm2: 0.18; AEC Qualified: N; VDC_V: 25V; AEC Category: Q200
R63 R166 = CMP-0027974-1: RES, 1.00 M, 1%, 0.05 W, 0201; Manufacturer: Yageo America; Power_W: 50mW; TempCo: 200 ppm/C; Value_Code: 1M00; U/M: EA; Value: 1.00Meg; EIA_Code: E96; Res_ohm: 1M; SizeX_mm: 0.6; SizeY_mm: 0.3; SizeZ_mm: 0.26; Value2: 0.05W; SizeArea_mm2: 0.18; AEC Qualified: N; VDC_V: 25V; AEC Category: Q200
R64 R107 R167 R170 = CMP-0028035-1: RES, 51.0 k, 1%, 0.05 W, 0201; Manufacturer: Yageo America; PartNumber: RC0201FR-7D51KL; Power_W: 50mW; TempCo: 200 ppm/C; Value_Code: 51k0; U/M: EA; Value: 51.0k; Res_ohm: 51k; SizeX_mm: 0.6; SizeY_mm: 0.3; SizeZ_mm: 0.26; Value2: 0.05W; SizeArea_mm2: 0.18; AEC Qualified: N; VDC_V: 25V; AEC Category: Q200
R105 R168 = CMP-0027574-1: RES, 2.00 M, 1%, 0.05 W, 0201; Manufacturer: Yageo America; Power_W: 50mW; TempCo: 200 ppm/C; Value_Code: 2M00; U/M: EA; Value: 2.00Meg; EIA_Code: E96; Res_ohm: 2M; SizeX_mm: 0.6; SizeY_mm: 0.3; SizeZ_mm: 0.26; Value2: 0.05W; SizeArea_mm2: 0.18; AEC Qualified: N; VDC_V: 25V; AEC Category: Q200
R108 R109 R128 R129 R132 R133 R135 R139 R146-R148 R171 = CMP-0027008-4: RES, 0, 5%, 0.05 W, 0201; Manufacturer: Vishay-Dale; Power_W: 50mW; TempCo: ppm/C; Value_Code: 0000; Value: 0; EIA_Code: E24; SizeX_mm: 0.6; SizeY_mm: 0.3; SizeZ_mm: 0.26; Value2: 0.05W; SizeArea_mm2: 0.18; AEC Qualified: N; AEC Category: Q200
R110 R118 R156 R158 R173 = CMP-0027719-1: RES, 470, 1%, 0.05 W, 0201; Manufacturer: Yageo America; Power_W: 50mW; TempCo: 200 ppm/C; Value_Code: 470R; U/M: EA; Value: 470; SizeX_mm: 0.6; SizeY_mm: 0.3; SizeZ_mm: 0.26; Value2: 0.05W; SizeArea_mm2: 0.18; AEC Qualified: N; VDC_V: 25V; AEC Category: Q200
R164 R172 = CMP-0083836-1: RES, 100, 1%, 0.05 W, 0201; Manufacturer: Vishay-Semiconductor; Value_Code: 100R; SizeAreaWB_mm2: 2.08; SizeArea_mm2: 0.18; AEC Qualified: N; AEC Category: Q200; Value: 100; SizeZ_mm: 0.26; EIA_Code: E96; TempCo: 100 ppm/C; Power_W: 50mW; SizeY_mm: 0.3; Value2: 0.05W; SizeX_mm: 0.6
TP1 TP2 TP4 TP5 TP15 TP16 = CMP-0078143-3: TEST POINT.  No entry in BOM.
U1 = CMP-0088521-10: Dual Port USB Type-C and USB PD Controller with Integrated Source Power Switches; Manufacturer: Texas instruments; TJmax_C: +125°C; Interface: I2C,USB; TaMin_C: -10°C; Number Of Ports: 2; AEC Category: Q200; Usb Standard: USB 3.0; SizeZ_mm: 1mm; Max Supply Voltage: 22V; Standoff Height: 0mm; TaMax_C: +65°C; CompType: IC; Min Supply Voltage: 0V
U2 = CMP-0005313-2: 256 kb I2C CMOS Serial EEPROM, SOIC-8; Manufacturer: ON Semiconductor; SizeAreaWB_mm2: 55.131; SizeZ_mm: 1.75; SizeX_mm: 5.99; SizeY_mm: 4.9; SizeArea_mm2: 29.351
U10 U25 = CMP-0088339-1: 2.7- 23V, 5.5 A Integrated Ideal Diode Power Switch with Input Reverse Polarity and Overvoltage Protection; Manufacturer: Texas Instruments; Standoff Height: 0mm; TJmax_C: +125°C; SizeZ_mm: 1mm; Output Voltage: 42V; Number Of Outputs: 1; AEC Qualified: No; Min Supply Voltage: 2.7V; Nominal Supply Current: 230uA

## Sheet ISFA375_DEBUG_MCU_TIVA.SchDoc
size 431 x 279 mm; Date: Not shown in title block; ApprovedBy: Not shown in title block; CheckedBy: Not shown in title block; Author: Not shown in title block; CompanyName: Not shown in title block; DrawnBy: Thomas Mauer; Engineer: Not shown in title block; Organization: Not shown in title block; Address1: Not shown in title block; Address2: Not shown in title block; Address3: Not shown in title block; Address4: Not shown in title block; DocumentNumber: 10; Revision: Use project parameter SCH_Rev; SheetNumber: 10; SheetTotal: 11; PageSetup: Record=PageOptions¦CenterHorizontal=True¦CenterVertical=True¦PrintScale=1.00¦XCorrection=1.00¦YCorrection=1.00¦PrintKind=0¦BorderSize=5000000¦LeftOffset=0¦BottomOffset=0¦Orientation=2¦PaperLength=1000¦PaperWidth=1000¦Scale=100¦PaperSource=15¦PrintQuality=600¦MediaType=1¦DitherType=10¦PaperKind=Letter¦PrintScaleMode=1
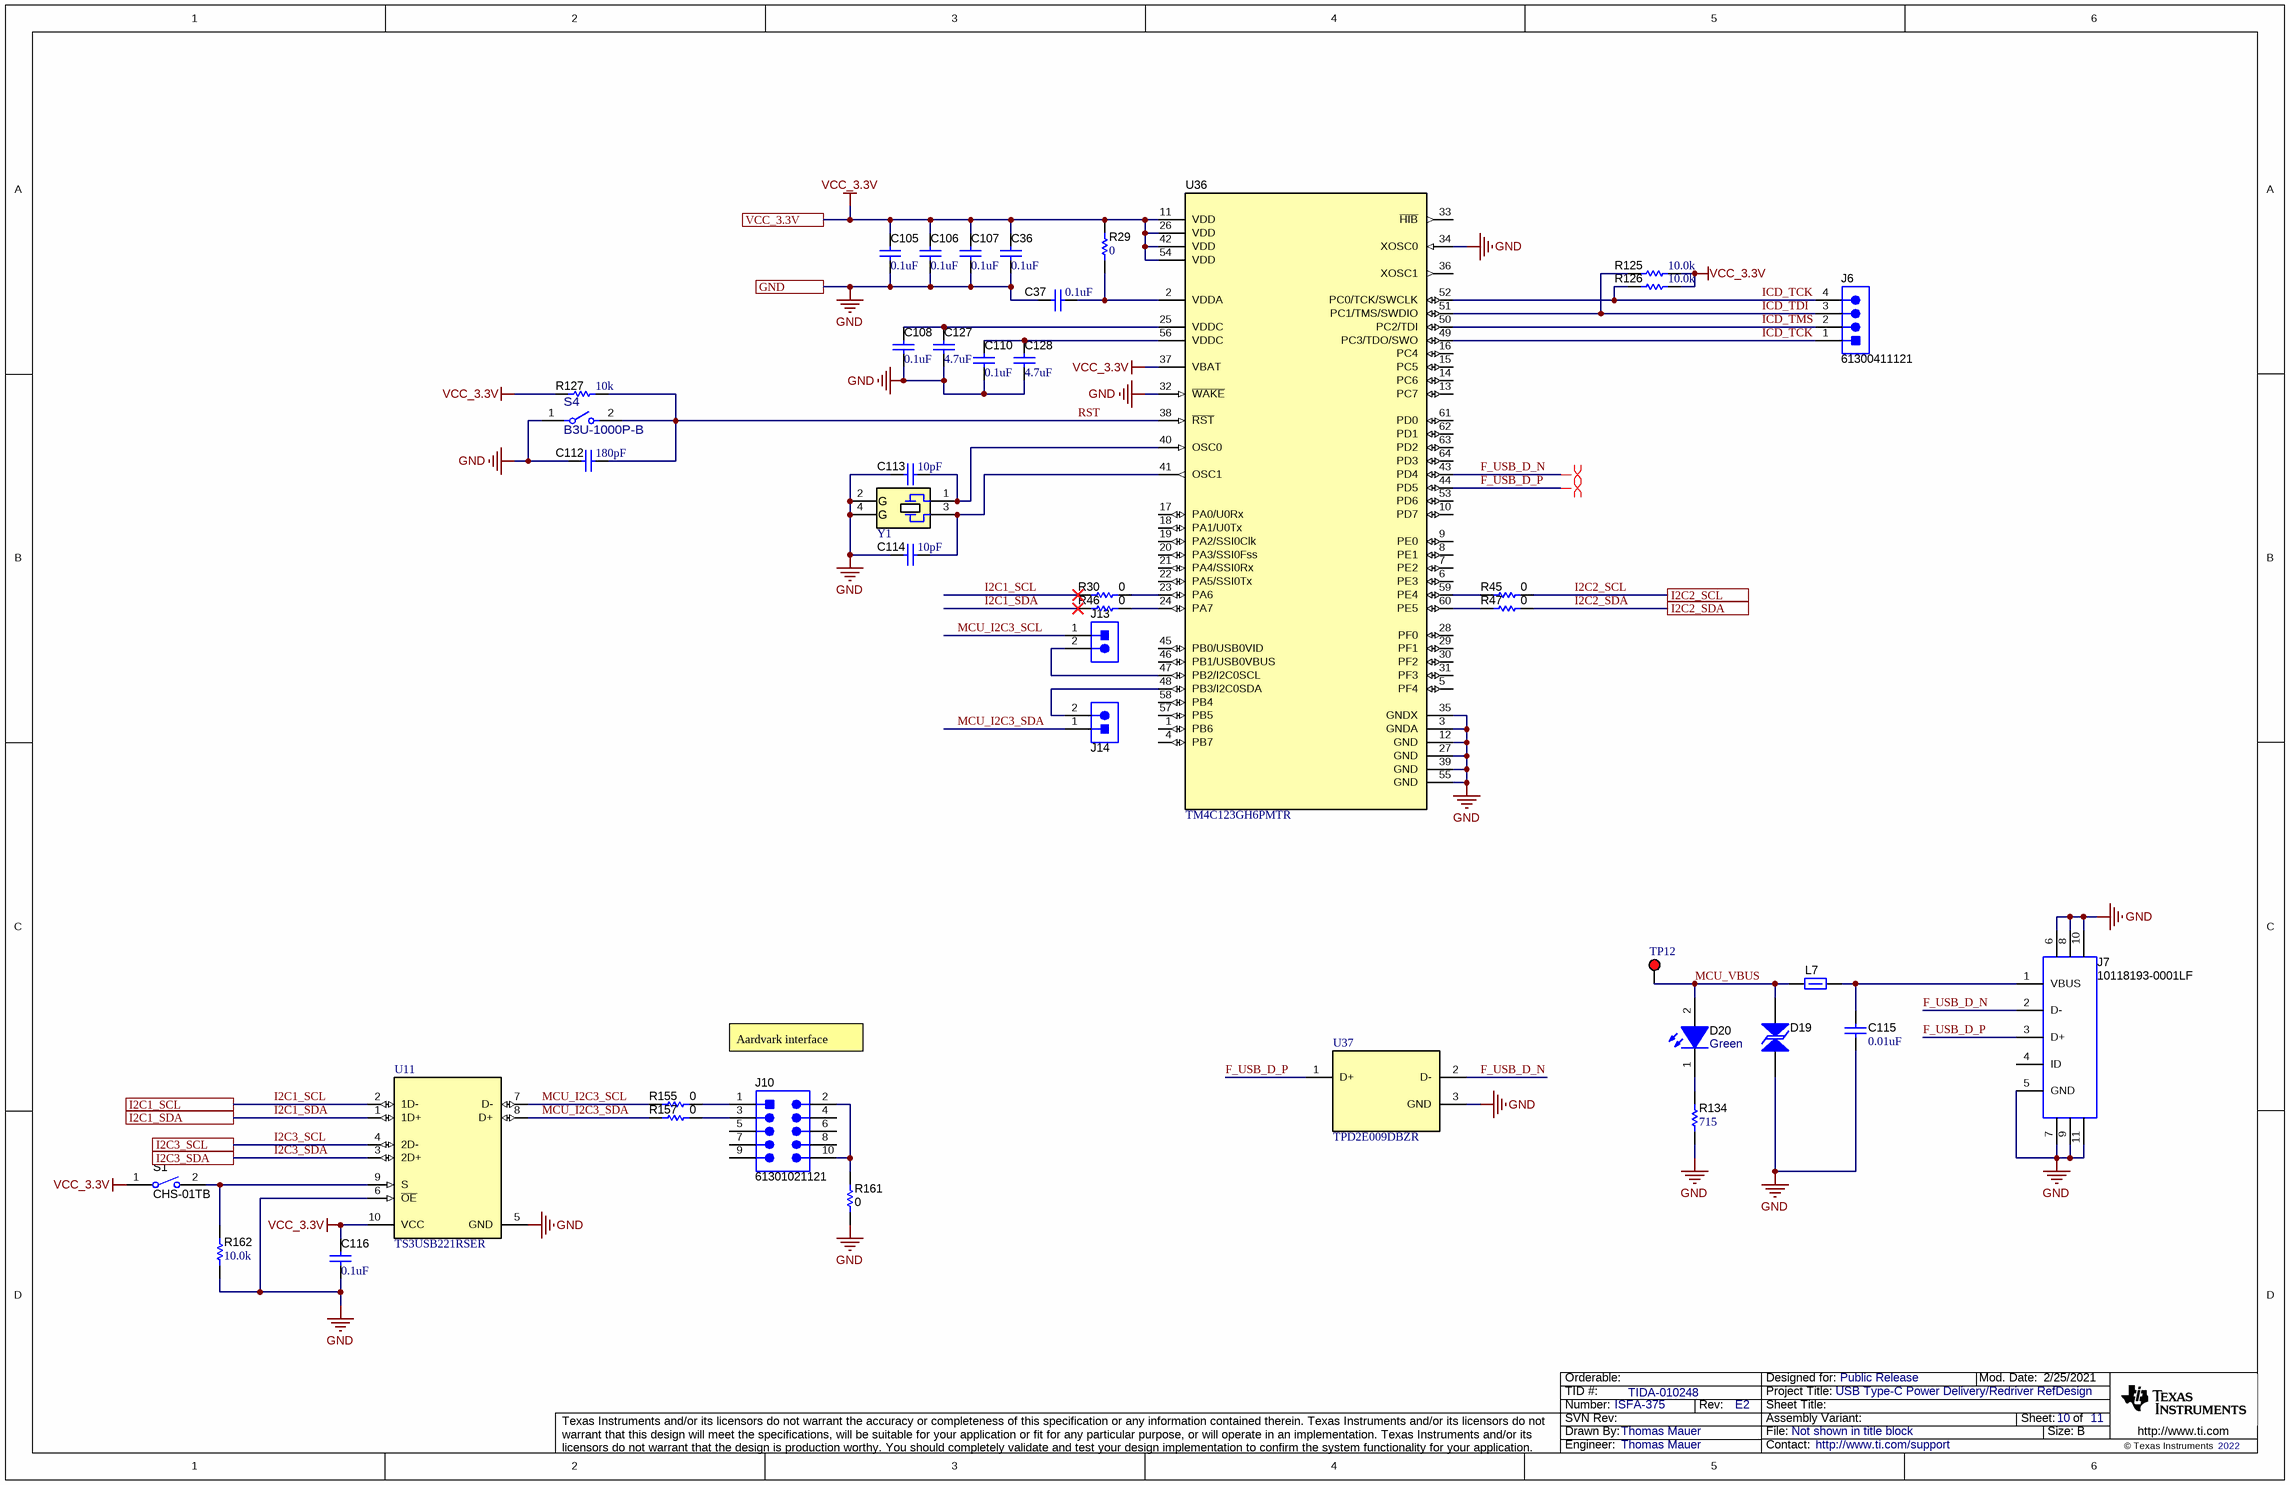
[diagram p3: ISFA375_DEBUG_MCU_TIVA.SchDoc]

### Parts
C36  ValueDisplayed: 0.1uF  [0201L]  (hidden comment: GRM033Z71C104KE14D)
C37  ValueDisplayed: 0.1uF  [0201L]  (hidden comment: GRM033Z71C104KE14D)
C105  ValueDisplayed: 0.1uF  [0201L]  (hidden comment: GRM033Z71C104KE14D)
C106  ValueDisplayed: 0.1uF  [0201L]  (hidden comment: GRM033Z71C104KE14D)
C107  ValueDisplayed: 0.1uF  [0201L]  (hidden comment: GRM033Z71C104KE14D)
C108  ValueDisplayed: 0.1uF  [0201L]  (hidden comment: GRM033Z71C104KE14D)
C110  ValueDisplayed: 0.1uF  [0201L]  (hidden comment: GRM033Z71C104KE14D)
C112  ValueDisplayed: 180pF  [0603L]  (hidden comment: 06035A181JAT2A)
C113  ValueDisplayed: 10pF  [0201L]  (hidden comment: GJM0335C1E100JB01D)
C114  ValueDisplayed: 10pF  [0201L]  (hidden comment: GJM0335C1E100JB01D)
C115  ValueDisplayed: 0.01uF  [0402L]  (hidden comment: C0402C103J5RACTU)
C116  ValueDisplayed: 0.1uF  [0201L]  (hidden comment: GRM033Z71C104KE14D)
C127  ValueDisplayed: 4.7uF  [0201L]  (hidden comment: GRM035R60J475ME15D)
C128  ValueDisplayed: 4.7uF  [0201L]  (hidden comment: GRM035R60J475ME15D)
D19  TPD1E1B04DPYR  [DPY0002A]  (value not drawn)
D20  value Green  [WL-SMCW_GREEN]  (hidden comment: 150060VS75000)
J6  61300411121  [WURTH_61300411121]
J7  10118193-0001LF  [FCI_10118193-0001LF]
J10  61301021121  [WURTH_61301021121]
J13  61300211121  [WURTH_61300211121]  (value not drawn)
J14  61300211121  [WURTH_61300211121]  (value not drawn)
L7  74279228260  [0603L]  (value not drawn)
R29  ValueDisplayed: 0  [0603L]  (hidden comment: CRCW06030000Z0EA)
R30  ValueDisplayed: 0  [0201L]  (hidden comment: CRCW02010000Z0ED)
R45  ValueDisplayed: 0  [0201L]  (hidden comment: CRCW02010000Z0ED)
R46  ValueDisplayed: 0  [0201L]  (hidden comment: CRCW02010000Z0ED)
R47  ValueDisplayed: 0  [0201L]  (hidden comment: CRCW02010000Z0ED)
R125  ValueDisplayed: 10.0k  [0201L]  (hidden comment: CRCW020110K0FKED)
R126  ValueDisplayed: 10.0k  [0201L]  (hidden comment: CRCW020110K0FKED)
R127  ValueDisplayed: 10k  [0402L]  (hidden comment: CRCW040210K0JNED)
R134  ValueDisplayed: 715  [0201]  (hidden comment: RC0201FR-07715RL)
R155  ValueDisplayed: 0  [0201L]  (hidden comment: CRCW02010000Z0ED)
R157  ValueDisplayed: 0  [0201L]  (hidden comment: CRCW02010000Z0ED)
R161  ValueDisplayed: 0  [0201L]  (hidden comment: CRCW02010000Z0ED)
R162  ValueDisplayed: 10.0k  [0201L]  (hidden comment: CRCW020110K0FKED)
S1  CHS-01TB  [SW_CHS-01TB]
S4  B3U-1000P-B  [FP-B3U-1000P-B_SMT_SW_3MM_2MM5-MFG]
TP12  5005  [Keystone5005]  (value not drawn)
U11  TS3USB221RSER  [RSE0010A]
U36  TM4C123GH6PMTR  [PM0064A_L]
U37  TPD2E009DBZR  [DBZ0003A_L]
Y1  NX3225GA-16.000M-STD-CRG-1  [NDK_NX3225GA]  (value not drawn)

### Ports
GND, I2C1_SCL, I2C1_SDA, I2C2_SCL, I2C2_SDA, I2C3_SCL, I2C3_SDA, VCC_3.3V

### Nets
GND: C36.2 C37.1 C105.2 C106.2 C107.2 C108.2 C110.2 C112.2 C113.2 C114.2 C115.1 C116.2 C127.2 C128.2 D19.1 J7.5(GND) J7.6 J7.7 J7.8 J7.9 J7.10 J7.11 R134.1 R161.1 R162.1 S4.1 U11.5(GND) U11.6(~{OE}) U36.3(GNDA) U36.12(GND) U36.27(GND) U36.32(~{WAKE}) U36.34(XOSC0) U36.35(GNDX) U36.39(GND) U36.55(GND) U37.3(GND) Y1.2(GND) Y1.4(GND) ; port GND
VCC_3.3V: C36.1 C105.1 C106.1 C107.1 C116.1 R29.2 R125.2 R126.2 R127.1 S1.1 U11.10(VCC) U36.11(VDD) U36.26(VDD) U36.37(VBAT) U36.42(VDD) U36.54(VDD) ; port VCC_3.3V
F_USB_D_N: J7.2(D-) U36.43(PD4) U37.2(D-)
F_USB_D_P: J7.3(D+) U36.44(PD5) U37.1(D+)
I2C1_SCL: R30.1 U11.2(1D-) ; port I2C1_SCL
I2C1_SDA: R46.1 U11.1(1D+) ; port I2C1_SDA
I2C2_SCL: R45.2 ; port I2C2_SCL
I2C2_SDA: R47.2 ; port I2C2_SDA
I2C3_SCL: U11.4(2D-) ; port I2C3_SCL
I2C3_SDA: U11.3(2D+) ; port I2C3_SDA
ICD_TCK: J6.1 J6.4 R126.1 U36.49(PC3/TDO/SWO) U36.52(PC0/TCK/SWCLK)
ICD_TDI: J6.3 R125.1 U36.51(PC1/TMS/SWDIO)
ICD_TMS: J6.2 U36.50(PC2/TDI)
MCU_I2C3_SCL: J13.1 R155.1 U11.7(D-)
MCU_I2C3_SDA: J14.1 R157.1 U11.8(D+)
MCU_VBUS: D19.2 D20.2(A) L7.1 TP12.1
RST: C112.1 R127.2 S4.2 U36.38(~{RST})
NetC37_2: C37.2 R29.1 U36.2(VDDA)
NetC108_1: C108.1 C127.1 U36.25(VDDC)
NetC110_1: C110.1 C128.1 U36.56(VDDC)
NetC113_1: C113.1 U36.40(OSC0) Y1.1
NetC114_1: C114.1 U36.41(OSC1) Y1.3
NetC115_2: C115.2 J7.1(VBUS) L7.2
NetD20_1: D20.1(K) R134.2
NetJ10_1: J10.1 R155.2
NetJ10_2: J10.2 J10.10 R161.2
NetJ10_3: J10.3 R157.2
NetJ13_2: J13.2 U36.47(PB2/I2C0SCL)
NetJ14_2: J14.2 U36.48(PB3/I2C0SDA)
NetR30_2: R30.2 U36.23(PA6)
NetR45_1: R45.1 U36.59(PE4)
NetR46_2: R46.2 U36.24(PA7)
NetR47_1: R47.1 U36.60(PE5)
NetR162_2: R162.2 S1.2 U11.9(S)

Not connected (* = marked no-connect by the designer): J7 4(ID); J10 4 5 6 7 8 9; U36 1(PB6) 4(PB7) 5(PF4) 6(PE3) 7(PE2) 8(PE1) 9(PE0) 10(PD7) 13(PC7) 14(PC6) 15(PC5) 16(PC4) 17(PA0/U0Rx) 18(PA1/U0Tx) 19(PA2/SSI0Clk) 20(PA3/SSI0Fss) 21(PA4/SSI0Rx) 22(PA5/SSI0Tx) 28(PF0) 29(PF1) 30(PF2) 31(PF3) 33(~{HIB}) 36(XOSC1) 45(PB0/USB0VID) 46(PB1/USB0VBUS) 53(PD6) 57(PB5) 58(PB4) 61(PD0) 62(PD1) 63(PD2) 64(PD3)

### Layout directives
differential pair; net class Diff_pairs: F_USB_D_N, F_USB_D_P

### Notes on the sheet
- Aardvark interface

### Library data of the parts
C36 C37 C105-C108 C110 C116 = CMP-0064970-1: CAP, CERM, 0.1 uF, 16 V,+/- 10%, X7R, 0201; Manufacturer: MuRata; TaMin_C: -55°C; Polarized: N; SizeAreaWB_mm2: 2.08; Value1: Unknown; U/M: EA; Value: 0.1uF; TaMax_C: 125°C; SizeZ_mm: 0.26; SizeX_mm: 0.6; SizeY_mm: 0.3; Cap_Case: 0201; Value2: 16V; SizeArea_mm2: 0.18; Cap_F: 100nF; AEC Category: Q200
C112 = CMP-0006770-4: CAP, CERM, 180 pF, 50 V, +/- 5%, C0G/NP0, 0603; Manufacturer: AVX; TaMin_C: -55°C; ESR_ohm: 0.09; Polarized: N; SizeAreaWB_mm2: 4.68; Value1: 0.09 ohm; U/M: EA; Value: 180pF; TaMax_C: 125°C; SizeZ_mm: 1; SizeX_mm: 1.6; SizeY_mm: 0.8; Cap_Case: 0603; Value2: 50V; SizeArea_mm2: 1.28; AEC Category: Q200
C113 C114 = CMP-0009661-3: CAP, CERM, 10 pF, 25 V, +/- 5%, C0G/NP0, 0201; Manufacturer: MuRata; TaMin_C: -55°C; Polarized: N; SizeAreaWB_mm2: 2.08; Value1: Unknown; U/M: EA; Value: 10pF; TaMax_C: 125°C; SizeZ_mm: 0.26; SizeX_mm: 0.6; SizeY_mm: 0.3; Cap_Case: 0201; Value2: 25V; SizeArea_mm2: 0.18; AEC Category: Q200
C115 = CMP-0006236-2: as C111 on sheet ISFA375_US_USB-C_CONN
C127 C128 = CMP-0009780-1: CAP, CERM, 4.7 uF, 6.3 V, +/- 20%, X5R, 0201; Manufacturer: MuRata; TaMin_C: -55°C; Polarized: N; SizeAreaWB_mm2: 2.08; Value1: Unknown; U/M: EA; Value: 4.7uF; TaMax_C: 85°C; SizeZ_mm: 0.26; SizeX_mm: 0.6; SizeY_mm: 0.3; Cap_Case: 0201; Value2: 6.3V; SizeArea_mm2: 0.18; Cap_F: 4.7µF; AEC Category: Q200
D19 = CMP-0073609-3: 1-Channel ESD Protection Diode With Low Dynamic Resistance and Low Clamping Voltage, DPY0002A (X1SON-2); Alternate PartNumber: TPD1E1B04DPYT; Manufacturer: Texas Instruments; SizeX_mm: 1.0; Rating: Catalog; SizeY_mm: 0.6; SizeAreaWB_mm2: 3.2; SizeZ_mm: 0.45; AEC Category: Q200; CompType: IC
D20 = CMP-0002894-2: as D1 on sheet ISFA375_PD_TPS65994
J6 = CMP-0054798-2: Header, 2.54 mm, 4x1, Gold, TH; Manufacturer: Wurth Elektronik; Pitch_mm: 2.54; Gender: Male; Row_Count: 1; Cert_UL: Y; Shrouded: N
J7 = CMP-0065029-1: Connector, Receptacle, USB Micro B, R/A, SMT; Manufacturer: FCI; CNHeader: False; Gender: Female; Row_Count: 1; Pitch_mm: 0.65; ContactFinish: Gold; CT: True
J10 = CMP-0054806-3: Header, 2.54 mm, 5x2, Gold, TH; Manufacturer: Wurth Elektronik; Green_Lifecycle: Active; Green_REACh: Passed; Cert_UL: Y; Current_A: 3A; Gender: Male; Pitch_mm: 2.54; Row_Count: 2; Shrouded: N; Voltage_V: 250V
J13 J14 = CMP-0054794-2: Header, 2.54 mm, 2x1, Gold, TH; Manufacturer: Wurth Elektronik; Shrouded: N; Gender: Male; Green_REACh: Passed; Pitch_mm: 2.54; Green_Lifecycle: Active; Row_Count: 1; Cert_UL: Y
L7 = CMP-0003155-2: Ferrite Bead, 26 ohm @ 100 MHz, 6.5 A, 0603; Manufacturer: Wurth Elektronik; Ztyp@1GHz_Ohm: 35.506; ZTyp@100MHz_Ohm: 26; SizeAreaWB_mm2: 4.68; DCR_ohm: 5m; Value1: 0.005 ohm; Value: 26 ohm; Imax_A: 6.5A; SizeZ_mm: 1; SizeX_mm: 1.6; SizeY_mm: 0.8; SizeArea_mm2: 1.28
R29 = CMP-0025697-4: RES, 0, 5%, 0.1 W, AEC-Q200 Grade 0, 0603; Manufacturer: Vishay-Dale; Power_W: 100mW; TempCo: 200 ppm/C; Value_Code: 0000; Value: 0; EIA_Code: E24; SizeX_mm: 1.6; SizeY_mm: 0.8; SizeZ_mm: 1; Value2: 0.1W; SizeArea_mm2: 1.28; AEC Qualified: Y; VDC_V: 75V; AEC Category: Q200
R30 R45-R47 R155 R157 R161 = CMP-0027008-4: as R108 on sheet ISFA375_PD_TPS65994
R125 R126 R162 = CMP-0027262-3: as R1 on sheet ISFA375_PD_TPS65994
R127 = CMP-0026825-5: RES, 10 k, 5%, 0.063 W, AEC-Q200 Grade 0, 0402; Manufacturer: Vishay-Dale; Power_W: 63mW; TempCo: 200 ppm/C; Value_Code: 10k0; Value: 10k; EIA_Code: E24; SizeX_mm: 1; SizeY_mm: 0.5; SizeZ_mm: 0.6; Value2: 0.063W; AEC Qualified: Y; VDC_V: 50V; AEC Category: Q200; AEC Grade: 0
R134 = CMP-0027857-1: RES, 715, 1%, 0.05 W, 0201; Manufacturer: Yageo America; Power_W: 50mW; TempCo: 200 ppm/C; Value_Code: 715R; U/M: EA; Value: 715; EIA_Code: E96; SizeX_mm: 0.6; SizeY_mm: 0.3; SizeZ_mm: 0.26; Value2: 0.05W; SizeArea_mm2: 0.18; AEC Qualified: N; VDC_V: 25V; AEC Category: Q200
S1 = CMP-0002163-2: Switch, Slide, SPST, Top Slide, SMT; Manufacturer: Copal Electronics; CurrentRating_mA: 100A; SwitchFunction: Off-On; VDC_V: 6V; PositionCount: 1
S4 = CMP-0095173-1: Tactile Switch SPST-NO Top Actuated Surface Mount; Manufacturer: Omron; Contact Current Rating: 50mA; Coil Resistance_ohm: 100mΩ; Electromechanical Life: 200000Cycles; AEC Qualified: No; SizeZ_mm: 1.75mm; TaMax_C: +70°C; Operating Force: 1.5N; VDC_V: 12V; TaMin_C: -25°C
TP12 = CMP-0055142-1: as TP9 on sheet ISFA375_US_USB-C_CONN
U11 = CMP-0033716-1: High-Speed USB 2.0 (480 Mbps) 1:2 Multiplexer / Demultiplexer Switch with Single Enable, 6 ohm RON, 2.5 to 3.3V, -40 to 85 degC, 10-Pin UQFN (RSE), Green (RoHS & no Sb/Br); Manufacturer: Texas Instruments; RON Flatness(Max)(Ohms): 1; IL OFF(Max)(nA): 2; Architecture: "1","2 mux/demux"; ron(max)(ohms): 6; RON Mis-match(Max)(Ohms): 0.2; OFF Time(Max)(ns): 12; Bandwidth(MHz): 1200; ON Time(Max)(ns): 30; SubFamily: USB Switch; tpd max(ns): 0.25; Vcc range(V): 2.3 to 3.6; ESD HBM(kV): +/-2
U36 = CMP-0029860-3: Tiva C Series Microcontroller, 256 KB Flash, 32 KB SRAM, 12 Bit, 12 Channels, -40 to 105 degC, 64-Pin LQFP (PM), Green (RoHS & no Sb/Br), Tape and Reel; Manufacturer: Texas Instruments; ADC Channels: 12; Prefix: Qualified Device; Data Memory: 32 KB; I2C: 2; Tiva Series: Connected MCUs; Max Speed: 80 MHz; UART: 4; ADC Resolution: 12 Bit; GPIOs: 43; Program Memory: 256 KB
U37 = CMP-0043101-1: ESD Protection Array for High-Speed Data Interfaces, 2 Channels, -40 to +85 degC, 3-pin SOT-23 (DBZ), Green (RoHS & no Sb/Br); Manufacturer: Texas Instruments; Serial ATA / eSATA: TRUE; IEC 61000-4-2 Contact(+/- kV): 8; Breakdown Voltage(Min)(V): 9; Differential Capacitance(pF): 0.01; IO Leakage Current(nA): 10; IO Capacitance(Typ)(pF): 0.7; SubFamily: ESD Solution
Y1 = CMP-0004635-3: Crystal, 16 MHz, 8pF, SMD; Manufacturer: NDK; TaMax_C: 70°C; TaMin_C: -10°C; Frequency Stability: +/-30ppm; Frequency_Fixed: 16MHz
